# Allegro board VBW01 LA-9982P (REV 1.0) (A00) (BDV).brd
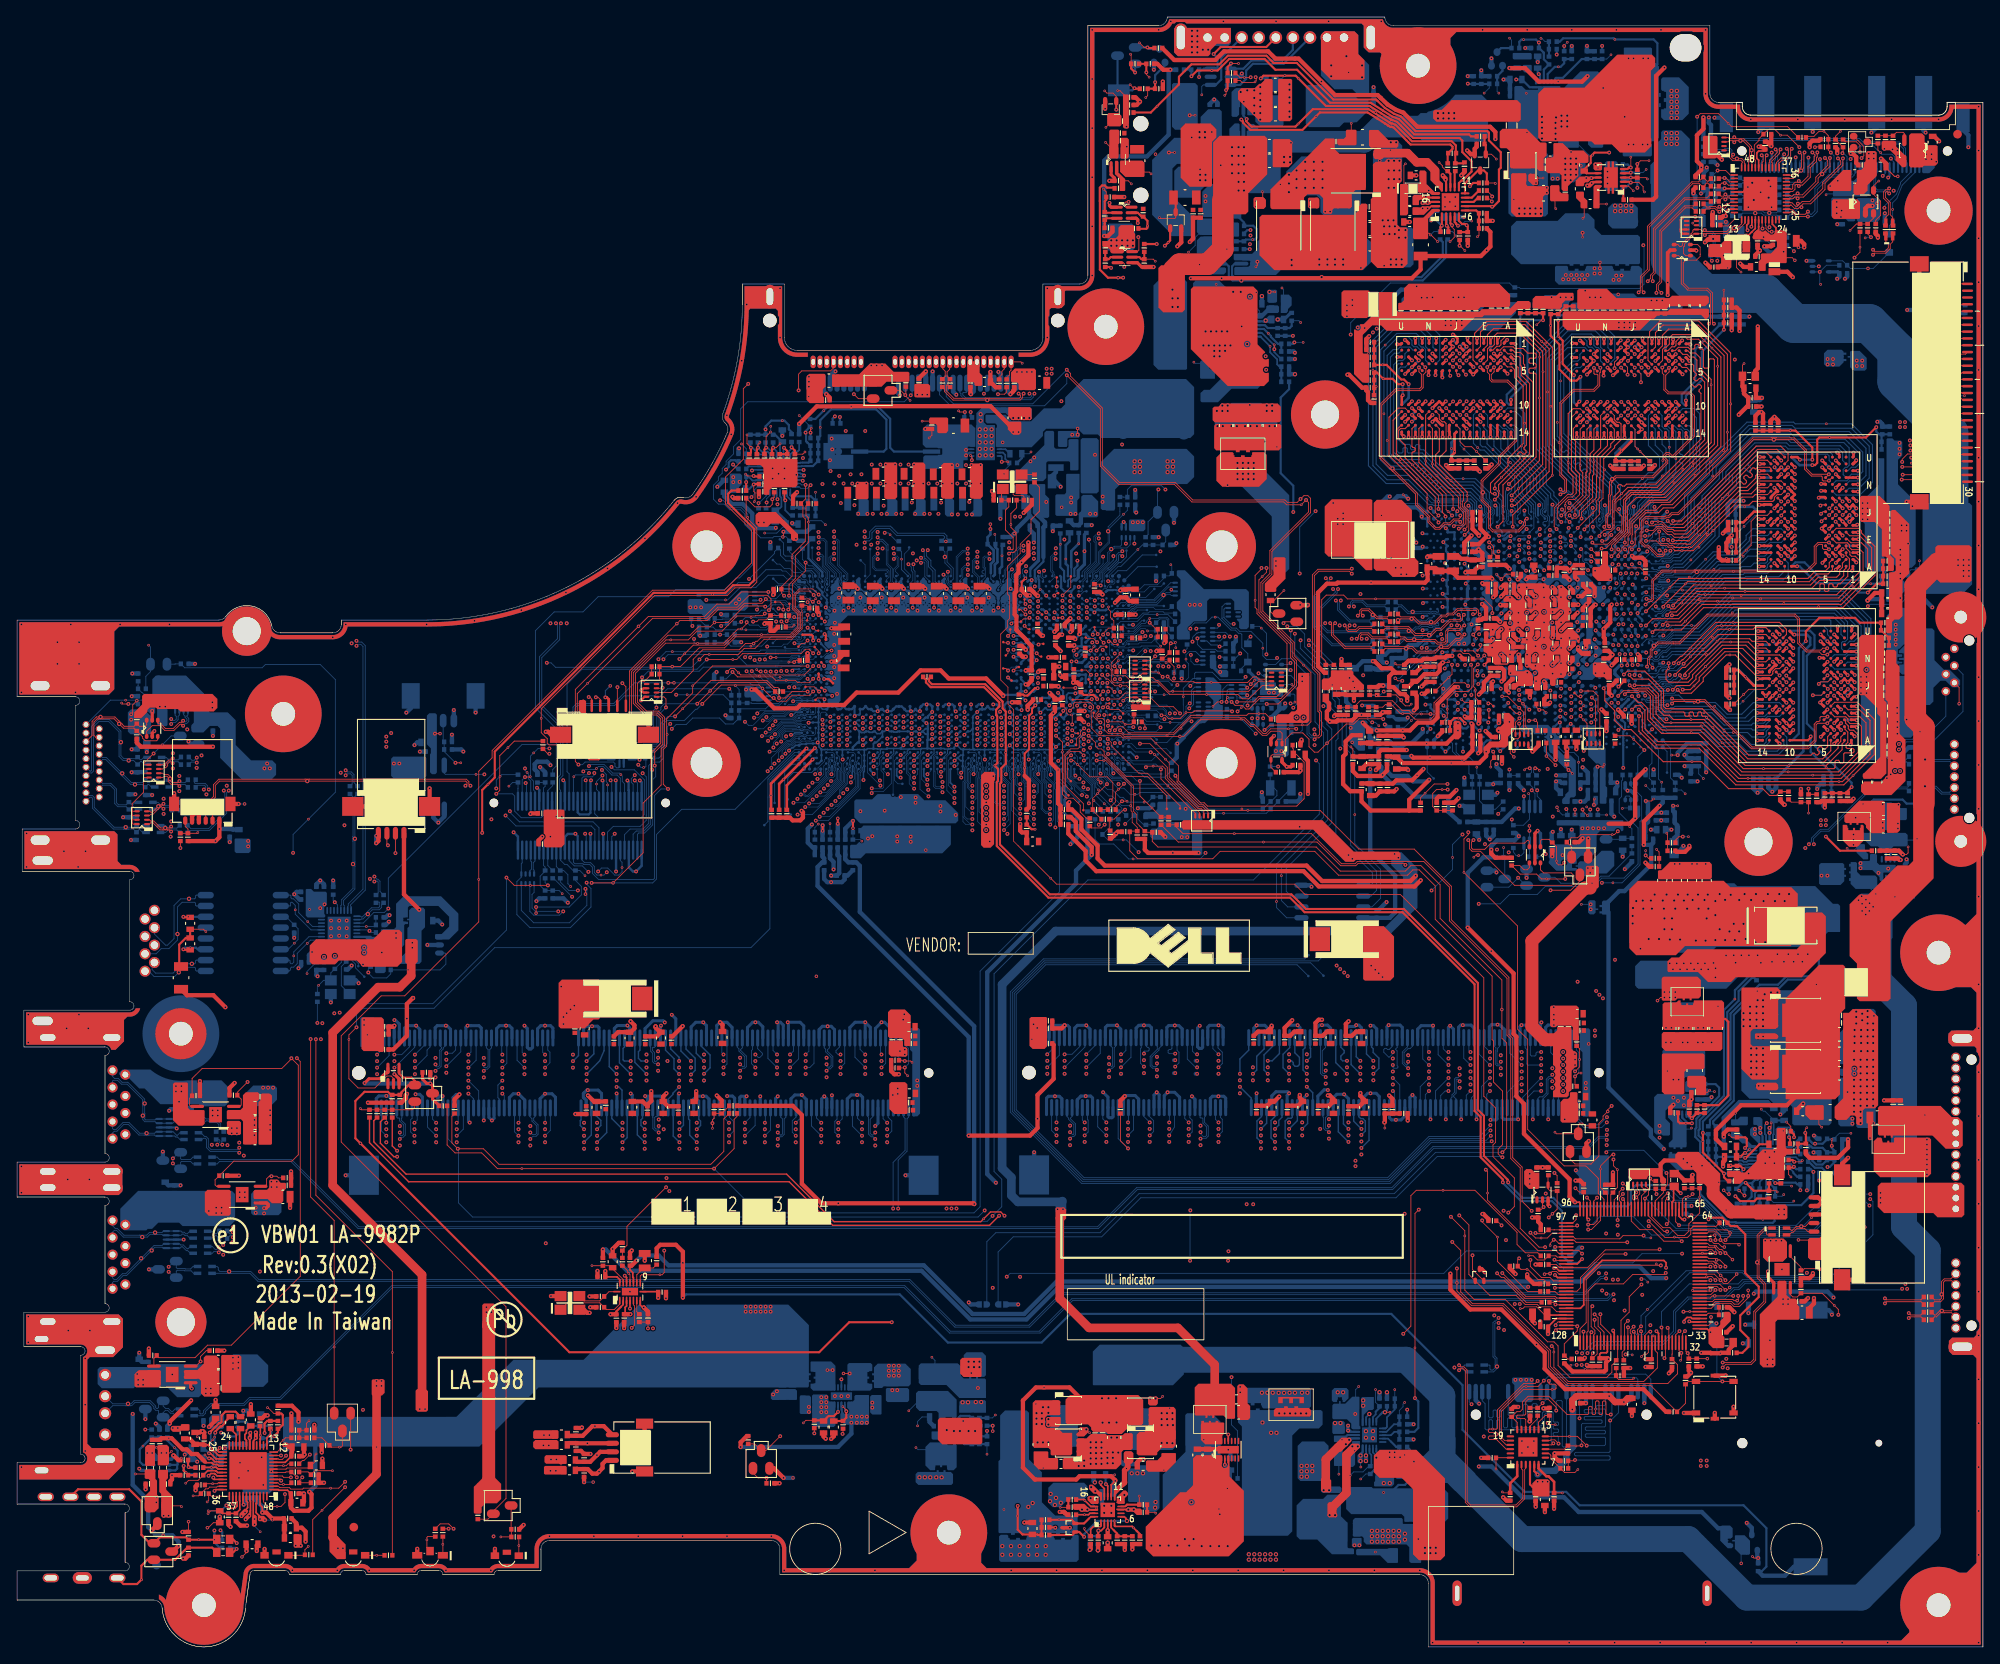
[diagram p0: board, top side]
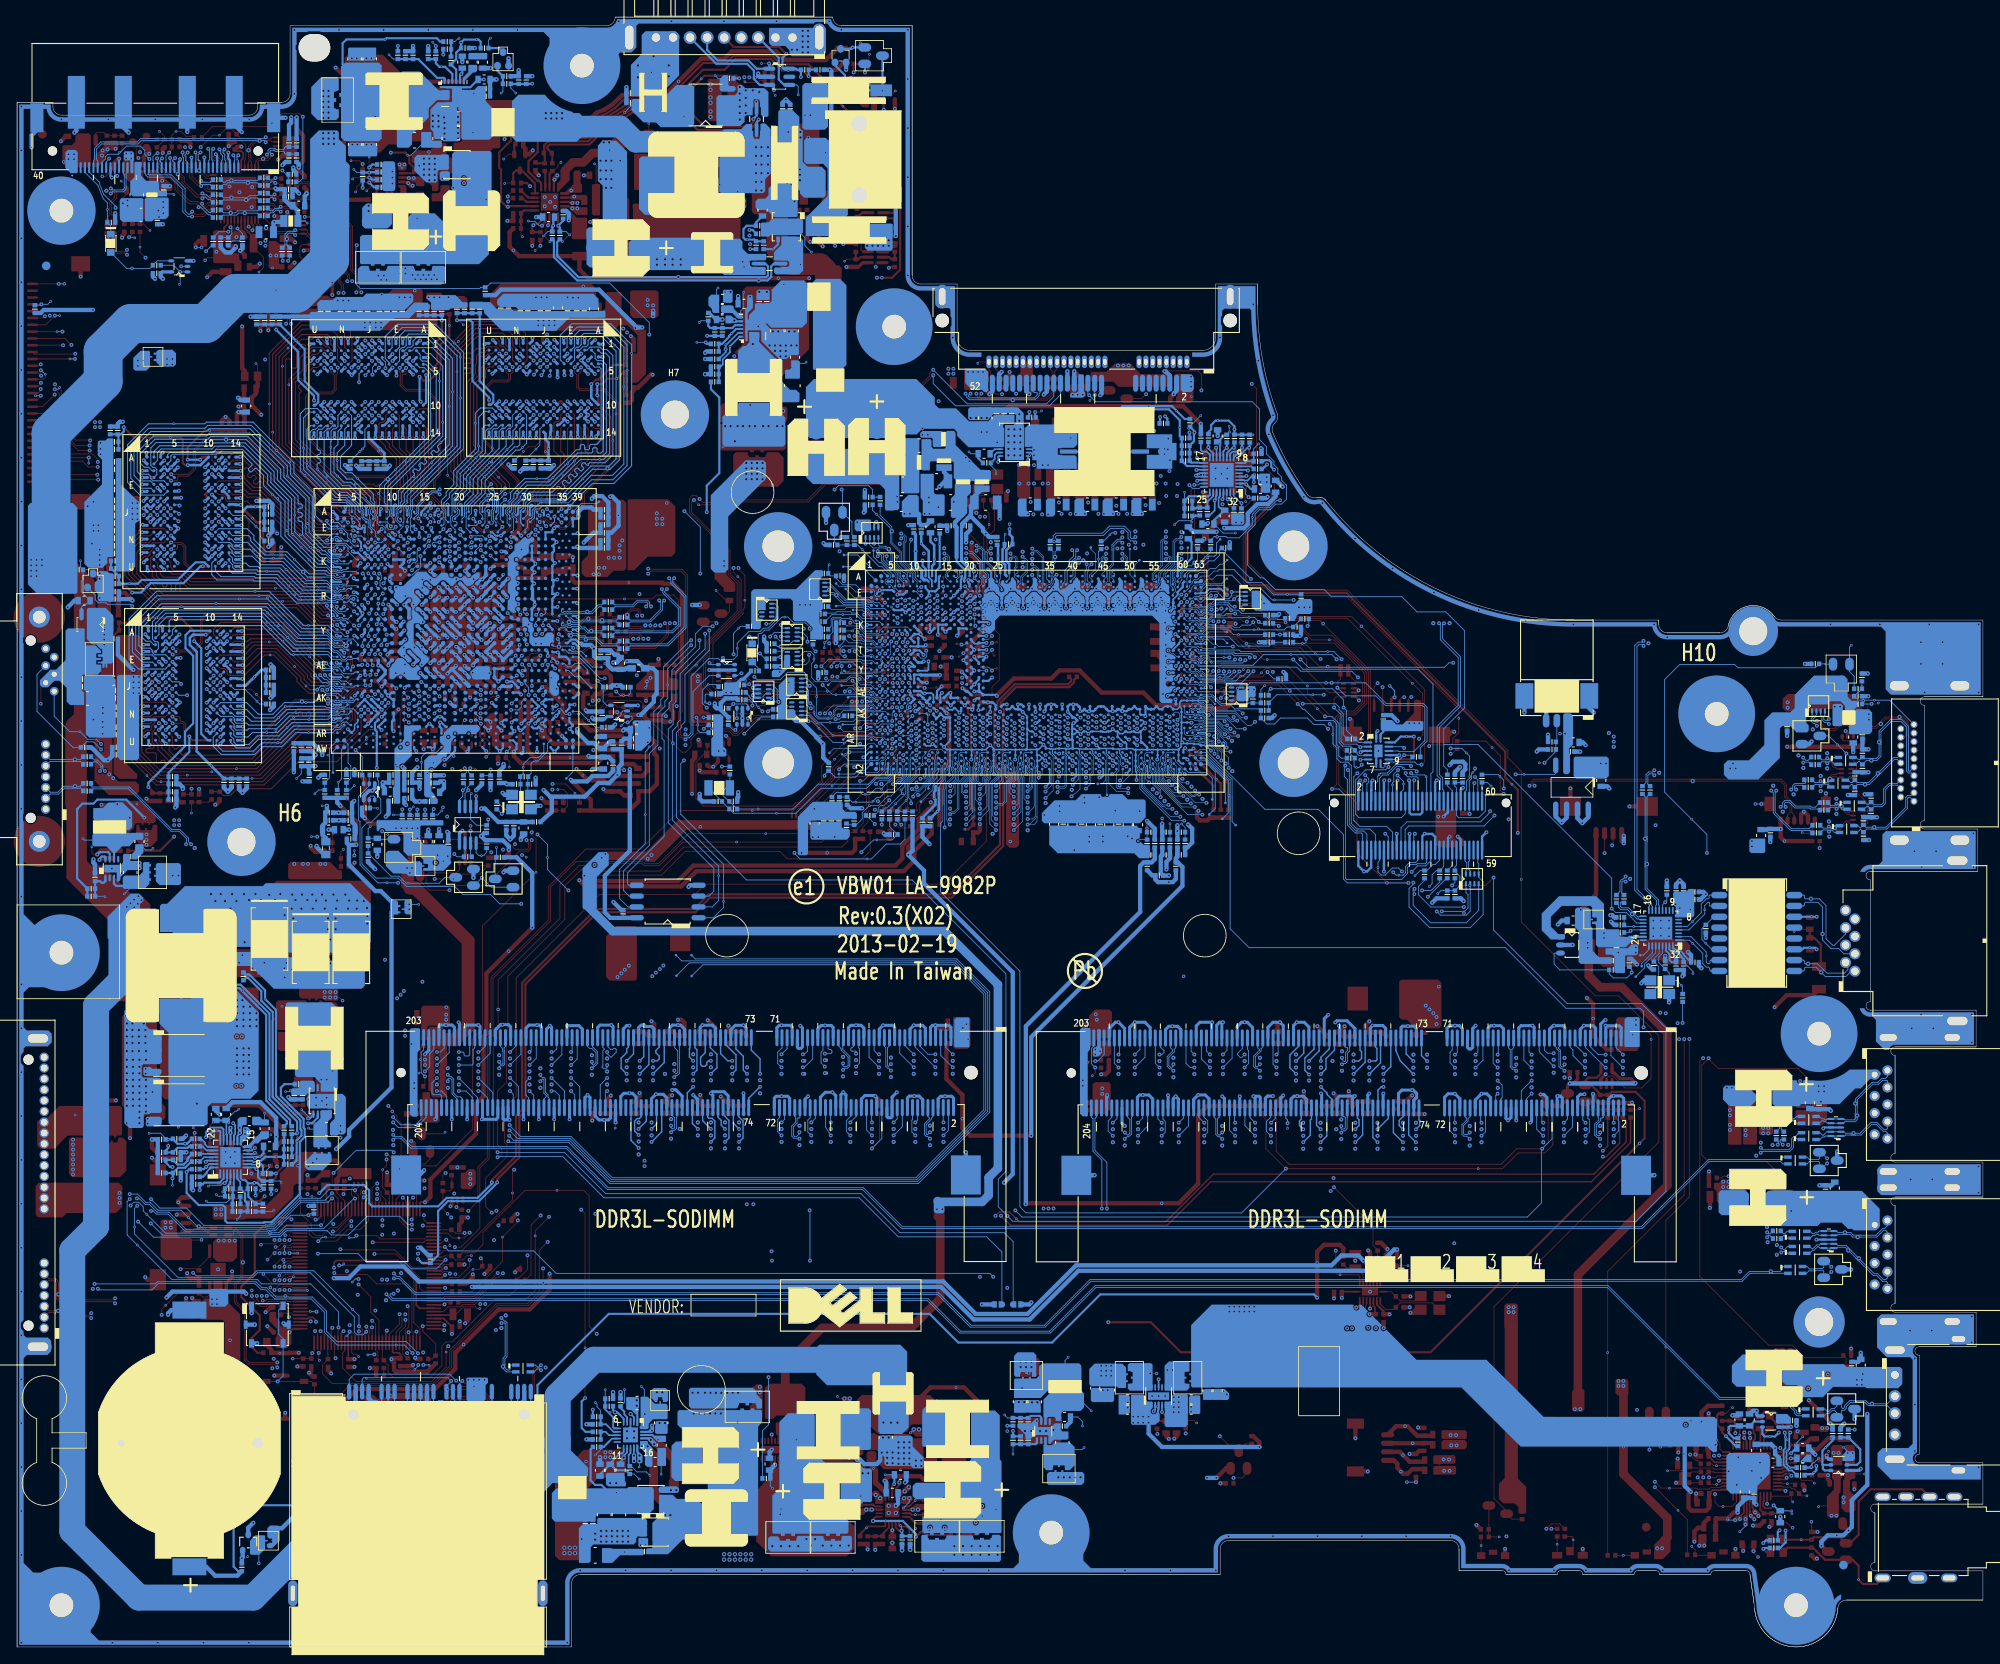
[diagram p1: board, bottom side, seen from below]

Outline 230.4 x 191.1 mm; copper layers: TOP, GND1, IN1, VCC, IN2, IN3, GND2, BOTTOM. Coordinates in mm from the lower left corner of the outline.

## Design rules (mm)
net group CLK_: nets CLK_CPU_ITP CLK_CPU_ITP#
net group CSI: nets CSIN CSIP
net group DIFFPAIR2: nets I2C1_SCL_TCH_PAD I2C1_SDA_TCH_PAD
net group DIFFPAIR3: nets CSCL CSDA
net group DIFFPAIR5: nets EC_SMB_CK2 EC_SMB_DA2
net group DIFFPAIR6: nets CPU_DPB_CTRLCLK_R CPU_DPB_CTRLDAT_R
net group DIFFPAIR9: nets CPU_EDP_AUX#_C CPU_EDP_AUX_C
net group EDID_CLK: nets EDID_CLK EDID_DATA
net group MIIC_SCL: nets MIIC_SCL MIIC_SDA
net group PCIE_PRX_LANTX_P3_C: nets PCIE_PRX_LANTX_N3_C PCIE_PRX_LANTX_P3_C
net group PECI-SINGLE: nets PECI_EC PECI_KB9012
net group SENSE: nets VCCSENSE VSSSENSE
net group SMB-15: nets SML1_SMBCLK SML1_SMBDATA
net group VCIN0_PH: nets ECAGND VCIN0_PH
net group WCKA0_0: nets WCKA0_0 WCKA0B_0
net group WCKA0_1: nets WCKA0_1 WCKA0B_1
net group WCKA1_0: nets WCKA1_0 WCKA1B_0
net group WCKA1_1: nets WCKA1_1 WCKA1B_1
net group WCKB0_0: nets WCKB0_0 WCKB0B_0
net group WCKB0_1: nets WCKB0_1 WCKB0B_1
net group WCKB1_0: nets WCKB1_0 WCKB1B_0
net group WCKB1_1: nets WCKB1_1 WCKB1B_1
net group 12: nets PCH_OPI_COMP PCH_PCIE_RCOMP SATA_IREF
net group ASYNC: nets DDR3_DRAMRST# DDR3_DRAMRST#_CPU H_PROCHOT# H_PROCHOT#_R H_VCCST_PWRGD_XDP XDP_OBS0_R XDP_OBS1_R
net group AUDIO: nets PCH_AZ_BITCLK PCH_AZ_CODEC_BITCLK PCH_AZ_CODEC_RST# PCH_AZ_CODEC_SDIN0 PCH_AZ_CODEC_SDOUT PCH_AZ_CODEC_SYNC PCH_AZ_RST# PCH_AZ_SDOUT PCH_AZ_SYNC
net group CLK: nets SUSCLK
net group CLK-SINGLE: nets CLK_PCI_LPC
net group CR_LOW: nets DSWODVREN INTRUDER# PCH_DPWROK PCH_INTVRMEN PCH_RSMRST#_R SYS_PWROK SYS_PWROK_R SYS_RESET#
net group DDRA-ADD: nets DDR_A_BS0 DDR_A_BS1 DDR_A_BS2 DDR_A_CAS# DDR_A_MA0 DDR_A_MA1 DDR_A_MA2 DDR_A_MA3 DDR_A_MA4 DDR_A_MA5 DDR_A_MA6 DDR_A_MA7 DDR_A_MA8 DDR_A_MA9 DDR_A_MA10 DDR_A_MA11 DDR_A_MA12 DDR_A_MA13 DDR_A_MA14 DDR_A_MA15 DDR_A_RAS# DDR_A_WE#
net group DDRA-CTL: nets DDR_CKE0_DIMMA DDR_CKE1_DIMMA DDR_CS0_DIMMA# DDR_CS1_DIMMA# M_ODT0 M_ODT1
net group DDRA-D0: nets DDR_A_D0 DDR_A_D1 DDR_A_D2 DDR_A_D3 DDR_A_D4 DDR_A_D5 DDR_A_D6 DDR_A_D7
net group DDRA-D1: nets DDR_A_D8 DDR_A_D9 DDR_A_D10 DDR_A_D11 DDR_A_D12 DDR_A_D13 DDR_A_D14 DDR_A_D15 DDR_A_DQS1 DDR_A_DQS#1
net group DDRA-D2: nets DDR_A_D16 DDR_A_D17 DDR_A_D18 DDR_A_D19 DDR_A_D20 DDR_A_D21 DDR_A_D22 DDR_A_D23
net group DDRA-D3: nets DDR_A_D24 DDR_A_D25 DDR_A_D26 DDR_A_D27 DDR_A_D28 DDR_A_D29 DDR_A_D30 DDR_A_D31
net group DDRA-D4: nets DDR_A_D32 DDR_A_D33 DDR_A_D34 DDR_A_D35 DDR_A_D36 DDR_A_D37 DDR_A_D38 DDR_A_D39
net group DDRA-D5: nets DDR_A_D40 DDR_A_D41 DDR_A_D42 DDR_A_D43 DDR_A_D44 DDR_A_D45 DDR_A_D46 DDR_A_D47
net group DDRA-D6: nets DDR_A_D48 DDR_A_D49 DDR_A_D50 DDR_A_D51 DDR_A_D52 DDR_A_D53 DDR_A_D54 DDR_A_D55
net group DDRA-D7: nets DDR_A_D56 DDR_A_D57 DDR_A_D58 DDR_A_D59 DDR_A_D60 DDR_A_D61 DDR_A_D62 DDR_A_D63
net group DDRB-ADD: nets DDR_B_BS0 DDR_B_BS1 DDR_B_BS2 DDR_B_CAS# DDR_B_MA0 DDR_B_MA1 DDR_B_MA2 DDR_B_MA3 DDR_B_MA4 DDR_B_MA5 DDR_B_MA6 DDR_B_MA7 DDR_B_MA8 DDR_B_MA9 DDR_B_MA10 DDR_B_MA11 DDR_B_MA12 DDR_B_MA13 DDR_B_MA14 DDR_B_MA15 DDR_B_RAS# DDR_B_WE#
net group DDRB-CTL: nets DDR_CKE2_DIMMB DDR_CKE3_DIMMB DDR_CS2_DIMMB# DDR_CS3_DIMMB# M_ODT2 M_ODT3
net group DDRB-D0: nets DDR_B_D0 DDR_B_D1 DDR_B_D2 DDR_B_D3 DDR_B_D4 DDR_B_D5 DDR_B_D6 DDR_B_D7
net group DDRB-D1: nets DDR_B_D8 DDR_B_D9 DDR_B_D10 DDR_B_D11 DDR_B_D12 DDR_B_D13 DDR_B_D14 DDR_B_D15
net group DDRB-D2: nets DDR_B_D16 DDR_B_D17 DDR_B_D18 DDR_B_D19 DDR_B_D20 DDR_B_D21 DDR_B_D22 DDR_B_D23
net group DDRB-D3: nets DDR_B_D24 DDR_B_D25 DDR_B_D26 DDR_B_D27 DDR_B_D28 DDR_B_D29 DDR_B_D30 DDR_B_D31
net group DDRB-D4: nets DDR_B_D32 DDR_B_D33 DDR_B_D34 DDR_B_D35 DDR_B_D36 DDR_B_D37 DDR_B_D38 DDR_B_D39
net group DDRB-D5: nets DDR_B_D40 DDR_B_D41 DDR_B_D42 DDR_B_D43 DDR_B_D44 DDR_B_D45 DDR_B_D46 DDR_B_D47
net group DDRB-D6: nets DDR_B_D48 DDR_B_D49 DDR_B_D50 DDR_B_D51 DDR_B_D52 DDR_B_D53 DDR_B_D54 DDR_B_D55
net group DDRB-D7: nets DDR_B_D56 DDR_B_D57 DDR_B_D58 DDR_B_D59 DDR_B_D60 DDR_B_D61 DDR_B_D62 DDR_B_D63
net group DP: nets CPU_DPB_AUX CPU_DPB_AUX# CPU_DPC_AUX CPU_DPC_AUX#
net group EDP: nets CPU_EDP_N0_C CPU_EDP_N1_C CPU_EDP_P0_C CPU_EDP_P1_C
net group HDA: nets AUD_HP_OUT_L_CN AUD_HP_OUT_R_CN HPOUT-L HPOUT-R MIC_IN MIC_IN_R RING2 RING2_R
net group HDMI: nets TMDS_L_TX0N TMDS_L_TX0P TMDS_L_TX1N TMDS_L_TX1P TMDS_L_TX2N TMDS_L_TX2P TMDS_L_TXCN TMDS_L_TXCP TMDS_TX0N TMDS_TX0P TMDS_TX1N TMDS_TX1P TMDS_TX2N TMDS_TX2P TMDS_TXCN TMDS_TXCP
net group KB: nets KSI0 KSI1 KSI2 KSI3 KSI4 KSI5 KSI6 KSI7 KSO0 KSO1 KSO2 KSO3 KSO4 KSO5 KSO6 KSO7 KSO8 KSO9 KSO10 KSO11 KSO12 KSO13 KSO14 KSO15 KSO16
net group LPC: nets LPC_LAD0 LPC_LAD1 LPC_LAD2 LPC_LAD3 LPC_LFRAME#
net group LVDS: nets EDP_AUX EDP_AUX# EDP_N0 EDP_N1 EDP_P0 EDP_P1 LVDS_A0+ LVDS_A0- LVDS_A1+ LVDS_A1- LVDS_A2+ LVDS_A2- LVDS_ACLK+ LVDS_ACLK- LVDS_B0+ LVDS_B0- LVDS_B1+ LVDS_B1- LVDS_B2+ LVDS_B2- LVDS_BCLK+ LVDS_BCLK-
net group PCIE: nets PCIE_PRX_LANTX_N3 PCIE_PRX_LANTX_P3 PCIE_PTX_LANRX_N3 PCIE_PTX_LANRX_P3 PCIE_PTX_WLANRX_N4_C PCIE_PTX_WLANRX_P4_C
net group PEG: nets PEG_CTX_GRX_N0 PEG_CTX_GRX_N1 PEG_CTX_GRX_N2 PEG_CTX_GRX_N3 PEG_CTX_GRX_P0 PEG_CTX_GRX_P1 PEG_CTX_GRX_P2 PEG_CTX_GRX_P3
net group POWER: nets +0.675VSP +1.5VS +1.5VSP +1.5VSP_ON +1.35VP +3V_WLAN +3VALW_PCH +3VALWP +3VLP +3VS_CAM +5V_HDD +5V_PVDD +5V_USB_PWR1 +5V_USB_PWR2 +5V_USB_PWR3 +5V_USB_PWR4 +5VA +5VALWP +5VS_ODD +5VS_TOUCH +AVCC33 +DIMM1_VREF_DQ +DIMM2_VREF_DQ +EC_VCCA +FAN_POWER +INV_PWR_SRC +LAN_IO +LAN_VDD +LCDVDD +MIC2-VREFO +PCH_VCCDSW +PCH_VCCDSW_R +RTCBATT +RTCVCC +SM_VREF_CA +SM_VREF_CA_DIMM +SM_VREF_DQ0 +SM_VREF_DQ0_DIMM1 +SM_VREF_DQ1 +SM_VREF_DQ1_DIMM2 +SW_LX +V18R +VCC_3IN1 +VCC_PWR_SRC +VCCIO_OUT +VCCIOA_OUT +VCHGR +VDISPLAY_VCC
net group RCOMP: nets SM_RCOMP0 SM_RCOMP1 SM_RCOMP2
net group RTC: nets PCH_RTCRST# PCH_RTCX1 PCH_RTCX2 SRTCRST#
net group SATA: nets SATA_PRX_DTX_N0 SATA_PRX_DTX_N0_C SATA_PRX_DTX_N1 SATA_PRX_DTX_P0 SATA_PRX_DTX_P0_C SATA_PRX_DTX_P1 SATA_PTX_DRX_N0 SATA_PTX_DRX_N1 SATA_PTX_DRX_P0 SATA_PTX_DRX_P1
net group SMB_10: nets DDR_XDP_SMBCLK_R1 DDR_XDP_SMBDAT_R1 SML0CLK SML0DATA
net group SPI: nets PCH_SPI_CLK PCH_SPI_CLK_R PCH_SPI_CS0# PCH_SPI_HOLD1# PCH_SPI_HOLD# PCH_SPI_MISO PCH_SPI_MISO_1 PCH_SPI_MOSI PCH_SPI_MOSI_1 PCH_SPI_WP1# PCH_SPI_WP#
net group SPK: nets INT-SPK-L+ INT-SPK-L- INT-SPK-R+ INT-SPK-R-
net group SVID: nets H_CPU_SVIDALRT# H_CPU_SVIDCLK H_CPU_SVIDDATA VR_SVID_ALRT# VR_SVID_CLK VR_SVID_DAT
net group THERMTRIP-SINGLE: nets H_THERMTRIP#
net group USB20: nets USB20_CAM_N7_R USB20_CAM_P7_R USB20_CR_N6_R USB20_CR_P6_R USB20_JUSB3_N2 USB20_JUSB3_N2_R USB20_JUSB3_P2 USB20_JUSB3_P2_R USB20_USBDB_N3_R USB20_USBDB_P3_R
net group USB30: nets USB3RN1_JUSB2 USB3RN1_JUSB2_R USB3RN2_JUSB1 USB3RN2_JUSB1_R USB3RP1_JUSB2 USB3RP1_JUSB2_R USB3RP2_JUSB1 USB3RP2_JUSB1_R USB3TN1_JUSB2_C USB3TN1_JUSB2_R USB3TN2_JUSB1_C USB3TN2_JUSB1_R USB3TP1_JUSB2_C USB3TP1_JUSB2_R USB3TP2_JUSB1_C USB3TP2_JUSB1_R
net group VRAMA1-D0: nets DDBIA1_0 DQA1_0 DQA1_1 DQA1_2 DQA1_3 DQA1_4 DQA1_5 DQA1_6 DQA1_7 EDCA1_0
net group VRAMA1-D1: nets DDBIA1_1 DQA1_8 DQA1_9 DQA1_10 DQA1_11 DQA1_12 DQA1_13 DQA1_14 DQA1_15 EDCA1_1
net group VRAMA1-D2: nets DDBIA1_2 DQA1_16 DQA1_17 DQA1_18 DQA1_19 DQA1_20 DQA1_21 DQA1_22 DQA1_23 EDCA1_2
net group VRAMA1-D3: nets DDBIA1_3 DQA1_24 DQA1_25 DQA1_26 DQA1_27 DQA1_28 DQA1_29 DQA1_30 DQA1_31 EDCA1_3
net group VRAMA-ADD: nets ADBIA0 ADBIA1 CASA0# CASA1# CKEA0 CKEA1 CSA0#_0 CSA1#_0 MAA0_0 MAA0_1 MAA0_2 MAA0_3 MAA0_4 MAA0_5 MAA0_6 MAA0_7 MAA0_8 MAA1_0 MAA1_1 MAA1_2 MAA1_3 MAA1_4 MAA1_5 MAA1_6 MAA1_7 MAA1_8 RASA0# RASA1# WEA0# WEA1#
net group VRAMA-D0: nets DDBIA0_0 DQA0_0 DQA0_1 DQA0_2 DQA0_3 DQA0_4 DQA0_5 DQA0_6 DQA0_7 EDCA0_0
net group VRAMA-D1: nets DDBIA0_1 DQA0_8 DQA0_9 DQA0_10 DQA0_11 DQA0_12 DQA0_13 DQA0_14 DQA0_15 EDCA0_1
net group VRAMA-D2: nets DDBIA0_2 DQA0_16 DQA0_17 DQA0_18 DQA0_19 DQA0_20 DQA0_21 DQA0_22 DQA0_23 EDCA0_2
net group VRAMA-D3: nets DDBIA0_3 DQA0_24 DQA0_25 DQA0_26 DQA0_27 DQA0_28 DQA0_29 DQA0_30 DQA0_31 EDCA0_3
net group VRAMB0-D0: nets DDBIB0_0 DQB0_0 DQB0_1 DQB0_2 DQB0_3 DQB0_4 DQB0_5 DQB0_6 DQB0_7 EDCB0_0
net group VRAMB0-D1: nets DDBIB0_1 DQB0_8 DQB0_9 DQB0_10 DQB0_11 DQB0_12 DQB0_13 DQB0_14 DQB0_15 EDCB0_1
net group VRAMB0-D2: nets DDBIB0_2 DQB0_16 DQB0_17 DQB0_18 DQB0_19 DQB0_20 DQB0_21 DQB0_22 DQB0_23 EDCB0_2
net group VRAMB0-D3: nets DDBIB0_3 DQB0_24 DQB0_25 DQB0_26 DQB0_27 DQB0_28 DQB0_29 DQB0_30 DQB0_31 EDCB0_3
net group VRAMB1-D0: nets DDBIB1_0 DQB1_0 DQB1_1 DQB1_2 DQB1_3 DQB1_4 DQB1_5 DQB1_6 DQB1_7 EDCB1_0
net group VRAMB1-D1: nets DDBIB1_1 DQB1_8 DQB1_9 DQB1_10 DQB1_11 DQB1_12 DQB1_13 DQB1_14 DQB1_15 EDCB1_1
net group VRAMB1-D2: nets DDBIB1_2 DQB1_16 DQB1_17 DQB1_18 DQB1_19 DQB1_20 DQB1_21 DQB1_22 DQB1_23 EDCB1_2
net group VRAMB1-D3: nets DDBIB1_3 DQB1_24 DQB1_25 DQB1_26 DQB1_27 DQB1_28 DQB1_29 DQB1_30 DQB1_31 EDCB1_3
net group VRAMB-ADD: nets ADBIB0 ADBIB1 CASB0# CASB1# CKEB0 CKEB1 CSB0#_0 CSB1#_0 DRAM_RST# DRAM_RST#_R MAB0_0 MAB0_1 MAB0_2 MAB0_3 MAB0_4 MAB0_5 MAB0_6 MAB0_7 MAB0_8 MAB1_0 MAB1_1 MAB1_2 MAB1_3 MAB1_4 MAB1_5 MAB1_6 MAB1_7 MAB1_8 RASB0# RASB1# WEB0# WEB1#
nets with their own width: min track width 0.254; nets +1.8VSP +3VALW +VGA_CORE +VGA_PCIEP CLK_BIASREF
nets with their own width: min track width 0.508; nets +0.675VS +1.2VSP_B+ +1.05V_PGOOD +1.05VS_APLLOPI +1.05VS_ASATA3PLL +1.05VS_AUSB3PLL +1.05VS_AXCK_DCB +1.05VS_AXCK_LCPLL +1.05VSP +1.8VGS +1.8VS +1.8VSP_ON +1.35V +1.35V_MEM_GFX +1.35VGPUP +1.35VS_VGA +3VALW_PCH_GATE +3VGS +3VS +3VS_RT +5VALW +5VS +AVDD +BIF_VDDC +CHGRTC +CPU_CORE +DPAB_VDD10 +DPAB_VDD18 +DPCD_VDD10 +DPCD_VDD18 +DPEF_VDD10 +DPEF_VDD18 +DPLL_PVDD +DPLL_VDDC +LCDVDD_CONN +MPV18 +PCIE_PVDD +PCIE_VDDR +SPV10 +SPV18 +TSVDD +VCCIO_OUT_R +VCCRTCEXT +VDD1DI +VDD_MEM15_REFDA +VDD_MEM15_REFDB +VDD_MEM15_REFSA +VDD_MEM15_REFSB +VDDC_CT +VDDCI +VDDCIP +VDDR4 +VREFG_GPU EDP_COMP GND GNDA
nets with their own width: min track width 1.016; nets +DVCC33
nets with their own width: min track width 1.27; nets +1.05VS
nets with their own width: min track width 1.524; nets +SWR_V12

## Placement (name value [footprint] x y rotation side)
C35  -  [C_0402NEW]  107.79 96.92 270 bottom
C36  -  [C_0402NEW]  105.63 96.92 270 bottom
C37  -  [C_0402NEW]  103.47 96.92 270 bottom
C38  -  [C_0402NEW]  101.31 96.92 270 bottom
C39  -  [C_0603NEW]  108.87 97.17 270 bottom
C41  -  [C_0603NEW]  106.71 97.1 270 bottom
C42  -  [C_0603NEW]  104.55 97.1 270 bottom
C45  -  [C_0603NEW]  102.39 97.1 270 bottom
C50  -  [C_0402NEW]  123.22 118.32 270 top
C51  -  [C_0402NEW]  149.5 105.74 0 top
C52  -  [C_0402NEW]  124.68 111.95 90 top
C53  -  [C_0402NEW]  124.55 119.68 180 top
C54  -  [C_0402NEW]  134.08 97.31 270 bottom
C55  -  [C_0402NEW]  134.97 97.31 270 bottom
C56  -  [C_0402NEW]  135.86 97.31 270 bottom
C57  -  [C_0402NEW]  130.34 121.04 180 top
C58  -  [C_0402NEW]  120.48 131.46 0 bottom
C59  -  [C_1206NEW]  119.66 134.19 0 bottom
C60  -  [C_0603NEW]  131.03 122.63 90 top
C61  -  [C_0402NEW]  122.79 119.71 180 top
C62  -  [C_0402NEW]  129.95 123.06 90 top
C63  -  [C_0402NEW]  125.31 130.62 90 bottom
C64  -  [C_0402NEW]  118.33 96.42 270 top
C65  -  [C_1206NEW]  125.44 134.06 0 bottom
C66  -  [C_0603NEW]  119.73 94.44 180 top
C67  -  [C_0402NEW]  119.99 111.07 180 top
C68  -  [C_0402NEW]  123.85 114.64 270 top
C69  -  [C_0402NEW]  118.9 114.51 270 top
C70  -  [C_1206NEW]  125.3 136.26 0 bottom
C71  -  [C_0402NEW]  121.69 118.39 270 top
C72  -  [C_0603NEW]  100.23 97.1 270 bottom
C73  -  [C_0402NEW]  122.72 116.03 180 top
C74  -  [C_0603NEW]  99.03 97.1 270 bottom
C75  -  [C_0402NEW]  117.43 110.75 90 top
C76  -  [C_0402NEW]  120.29 112.66 0 top
C77  -  [C_0402NEW]  121.63 110.17 90 top
C78  -  [C_0603NEW]  122.9 113.74 180 top
C81  -  [C_0402NEW]  124.46 109.75 270 top
C82  -  [C_0603NEW]  122.9 114.95 180 top
C83  -  [C_0402NEW]  119.6 119.97 270 top
C84  -  [C_1206NEW]  121.3 136.66 0 bottom
C85  -  [C_0402NEW]  119.61 131.46 180 bottom
C86  -  [C_1206NEW]  118.2 134.19 180 bottom
C87  -  [C_0402NEW]  120.3 113.54 90 top
C88  -  [C_0402NEW]  117.5 117.37 270 top
C2305  -  [C_0603NEW]  99.53 29.03 0 bottom
C2306  -  [C_0603NEW]  99.53 27.82 0 bottom
C2307  -  [C_0805NEW]  102.58 30.96 270 bottom
C2308  -  [C_0603NEW]  104.04 31.06 270 bottom
C2309  -  [C_0603NEW]  95.72 26.49 270 top
C2310  -  [C_0805NEW]  142.31 27.51 0 top
C2311  -  [C_0603NEW]  138.33 21.79 90 top
C2312  -  [C_0603NEW]  142.21 29.03 0 top
C2313  -  [C_0603NEW]  139.54 21.79 90 top
C2314  -  [C_0603NEW]  142.21 20.74 90 bottom
C2316  -  [C_0603NEW]  93.5 27.82 180 bottom
C2318  -  [C_0603NEW]  93.5 29.03 180 bottom
C2322  -  [C_0603NEW]  94.52 26.49 270 top
C2323  -  [C_0603NEW]  89.69 30.74 270 bottom
C2324  -  [C_0603NEW]  90.9 30.74 270 bottom
C2326  -  [C_0402NEW]  142.55 114.97 180 bottom
C2327  -  [C_0402NEW]  159.36 85.48 90 bottom
C5212  -  [C_0402NEW]  83.2 117.8 0 bottom
CA1  -  [C_0603NEW]  28.54 25.92 90 bottom
CA2  -  [C_0603NEW]  27.33 25.92 90 bottom
CA21  -  [C_0402NEW]  34.43 20.2 0 top
CA22  -  [C_0402NEW]  34.43 19.25 0 top
CA23  -  [C_0603NEW]  20.41 22.11 0 bottom
CA24  -  [C_0402NEW]  22.46 17.98 180 top
CA25  -  [C_0402NEW]  21.1 19 0 top
CA29  -  [C_0402NEW]  65.5 24.76 90 top
CA30  -  [C_0402NEW]  65.5 23.9 270 top
CA31  -  [C_0402NEW]  66.45 21.71 90 top
CA32  -  [C_0402NEW]  66.45 20.85 270 top
CA33  -  [C_0402NEW]  20.09 12.57 90 top
CA38  -  [C_0402NEW]  15.98 19.12 180 top
CA39  -  [C_0402NEW]  20.09 11.64 270 top
CA40  -  [C_0402NEW]  17.05 19.09 0 top
CA51  -  [C_0402NEW]  21.94 23.68 90 top
CA53  -  [C_0603NEW]  27.91 17.47 90 bottom
CA54  -  [C_0402NEW]  26.83 17.46 90 bottom
CA55  -  [C_0603NEW]  31.33 13.98 0 top
CA56  -  [C_0402NEW]  31.26 15.06 0 top
CA57  -  [C_0603NEW]  32.1 16.9 0 top
CA58  -  [C_0402NEW]  32.08 17.98 0 top
CA59  -  [C_0603NEW]  32.22 23.44 0 top
CA60  -  [C_0402NEW]  32.15 22.36 0 top
CA61  -  [C_0603NEW]  23.75 15.96 270 top
CA62  -  [C_0603NEW]  20.41 23.32 0 bottom
CA63  -  [C_0603NEW]  23.75 14.56 90 bottom
CA64  -  [C_0603NEW]  35.78 21.28 180 top
CA65  -  [C_0402NEW]  32.15 24.52 0 top
CA67  -  [C_0603NEW]  24.98 25.6 90 top
CA68  -  [C_0603NEW]  26.19 25.6 90 top
CA69  -  [C_0402NEW]  33.06 25.41 180 top
CA71  -  [C_0603NEW]  20.86 23.76 90 top
CA74  -  [C_0603NEW]  27.4 25.92 90 top
CC1  -  [C_0402NEW]  146 99.13 0 bottom
CC2  -  [C_0402NEW]  148.7 99.13 180 bottom
CC3  -  [C_0402NEW]  129.49 95.58 0 top
CC4  -  [C_0402NEW]  133.96 95.51 180 top
CC5  -  [C_0402NEW]  127.21 95.26 0 bottom
CC6  -  [C_0402NEW]  118.92 134.46 180 top
CC7  -  [C_0402NEW]  114.45 134.46 0 top
CC8  -  [C_0402NEW]  97.05 95.53 0 bottom
CC9  -  [C_0402NEW]  94.41 95.53 180 bottom
CC10  -  [C_0402NEW]  96.19 95.53 180 bottom
CC11  -  [C_0402NEW]  149.5 103.39 0 top
CC13  -  [C_0402NEW]  70.27 108.34 90 bottom
CC14  -  [C_0402NEW]  61.95 97.74 180 top
CC15  -  [C_0402NEW]  62.03 94.13 180 top
CC16  -  [C_0402NEW]  61.89 88.68 270 bottom
CC17  -  [C_0402NEW]  61.89 101.36 90 bottom
CC18  -  [C_0402NEW]  158.88 117.94 0 bottom
CC19  -  [C_0402NEW]  158.88 117.05 0 bottom
CC20  -  [C_0402NEW]  160.66 119.46 0 bottom
CC21  -  [C_0402NEW]  160.66 118.57 0 bottom
CC22  -  [C_0402NEW]  158.88 120.73 0 bottom
CC23  -  [C_0402NEW]  158.88 119.84 0 bottom
CC24  -  [C_0402NEW]  160.66 122.51 0 bottom
CC25  -  [C_0402NEW]  160.66 121.62 0 bottom
CC26  -  [C_0603NEW]  136.93 97.29 270 bottom
CC32  -  [C_0402NEW]  39.91 100.01 90 bottom
CC40  -  [C_0402NEW]  39.02 100.01 90 bottom
CD1  -  [C_0402NEW]  42.62 71.83 0 top
CD2  -  [C_0402NEW]  42.62 72.72 0 top
CD3  -  [C_0402NEW]  51.27 62.55 90 top
CD4  -  [C_0402NEW]  73.88 62.48 90 top
CD5  -  [C_0402NEW]  68.99 63.05 90 top
CD6  -  [C_0402NEW]  66.7 63.4 270 top
CD7  -  [C_0402NEW]  65.37 72.01 90 top
CD8  -  [C_0402NEW]  69.94 70.67 90 top
CD9  -  [C_0402NEW]  77.5 62.48 90 top
CD10  -  [C_0402NEW]  76.7 70.69 90 top
CD11  -  [C_0402NEW]  73.63 70.67 90 top
CD12  -  [C_0603NEW]  75.72 62.56 90 top
CD13  -  [C_0603NEW]  75.47 70.69 90 top
CD14  -  [C_0603NEW]  82.68 70.76 90 top
CD15  -  [C_D3]  73.27 76.02 180 top
CD16  -  [C_0603NEW]  67.91 62.56 90 top
CD17  -  [C_0603NEW]  72.1 62.56 90 top
CD18  -  [C_0603NEW]  79.34 62.56 90 top
CD19  -  [C_0603NEW]  66.51 71.77 90 top
CD20  -  [C_0603NEW]  71.78 70.69 90 top
CD21  -  [C_0402NEW]  81.69 62.55 90 top
CD22  -  [C_0402NEW]  82.58 62.55 90 top
CD23  -  [C_0402NEW]  47.51 67.36 0 top
CD24  -  [C_0402NEW]  105.26 70.75 180 top
CD25  -  [C_0402NEW]  105.26 71.64 180 top
CD26  -  [C_0402NEW]  105.01 62.94 180 top
CD27  -  [C_0402NEW]  104.94 63.83 180 top
CD28  -  [C_0603NEW]  105.29 64.91 180 top
CD29  -  [C_0603NEW]  105.25 72.72 180 top
CD30  -  [C_0402NEW]  102.58 70.74 90 top
CD31  -  [C_0402NEW]  103.47 70.74 90 top
CD32  -  [C_0402NEW]  120.41 73.42 0 top
CD33  -  [C_0402NEW]  120.41 72.53 0 top
CD34  -  [C_0402NEW]  129.31 62.55 90 top
CD35  -  [C_0402NEW]  152.49 62.55 90 top
CD36  -  [C_0402NEW]  148.87 62.55 90 top
CD37  -  [C_0402NEW]  145.25 62.55 90 top
CD38  -  [C_0402NEW]  156.05 62.48 90 top
CD39  -  [C_0402NEW]  155.73 70.74 90 top
CD40  -  [C_0402NEW]  152.17 70.74 90 top
CD41  -  [C_0402NEW]  148.56 70.74 90 top
CD42  -  [C_0402NEW]  144.94 70.74 90 top
CD43  -  [C_0603NEW]  150.65 62.56 90 top
CD44  -  [C_0603NEW]  147.03 62.56 90 top
CD45  -  [C_0603NEW]  154.27 62.56 90 top
CD46  -  [C_0603NEW]  146.78 70.75 90 top
CD47  -  [C_0603NEW]  150.33 70.75 90 top
CD48  -  [C_0603NEW]  153.95 70.75 90 top
CD49  -  [C_0603NEW]  157.57 70.75 90 top
CD50  -  [C_0603NEW]  157.89 62.56 90 top
CD51  -  [C_D3]  152.68 82.98 0 top
CD52  -  [C_0402NEW]  160.3 62.55 90 top
CD53  -  [C_0402NEW]  161.19 62.55 90 top
CD54  -  [C_0402NEW]  183.62 72.27 180 top
CD55  -  [C_0402NEW]  183.62 73.16 180 top
CD56  -  [C_0402NEW]  183.56 62.56 180 top
CD57  -  [C_0402NEW]  183.56 63.45 180 top
CD58  -  [C_0603NEW]  183.83 64.53 180 top
CD59  -  [C_0603NEW]  183.54 74.24 180 top
CD60  -  [C_0402NEW]  180.94 72.26 90 top
CD61  -  [C_0402NEW]  181.83 72.26 90 top
CE1  -  [C_0402NEW]  199.41 36.9 0 top
CE2  -  [C_0402NEW]  191.54 33.74 270 top
CE5  -  [C_0402NEW]  178.51 37.54 0 top
CE6  -  [C_0402NEW]  185.49 32.93 90 top
CE7  -  [C_0402NEW]  200.61 34.49 0 top
CE8  -  [C_0402NEW]  196.31 53.78 90 top
CE9  -  [C_0402NEW]  200.45 49.73 180 top
CE11  -  [C_0402NEW]  199.47 39.83 0 top
CE12  -  [C_0402NEW]  187.4 31.82 0 top
CE15  -  [C_0402NEW]  178.08 55.31 90 top
CE16  -  [C_0805NEW]  179.31 39 180 top
CE18  -  [C_0402NEW]  178.58 44.84 0 top
CE19  -  [C_0402NEW]  179.48 55.31 90 top
CE20  -  [C_0402NEW]  195.55 30.8 90 top
CE22  -  [C_0603NEW]  48.73 106.06 180 bottom
CE23  -  [C_0402NEW]  48.81 104.98 180 bottom
CE24  -  [C_0402NEW]  50.05 106.12 0 bottom
CE25  -  [C_0603NEW]  44.73 102.31 270 bottom
CE26  -  [C_0402NEW]  183.61 53.34 90 top
CE27  -  [C_0402NEW]  184.62 33.84 270 top
CE28  -  [C_0402NEW]  188.31 33.61 270 top
CE29  -  [C_0402NEW]  193.96 33.74 270 top
CE30  -  [C_0402NEW]  175.87 44.65 180 top
CE31  -  [C_0402NEW]  196.85 33.81 270 top
CE32  -  [C_0402NEW]  173.36 49.97 180 top
CE33  -  [C_0402NEW]  182.2 33.77 0 top
CG1  -  [C_0402NEW]  71.83 44.7 90 top
CG2  -  [C_0402NEW]  71.15 39.01 270 top
CG3  -  [C_0402NEW]  75.14 41.6 0 top
CG4  -  [C_0402NEW]  68.94 43.38 180 top
CG5  -  [C_0805NEW]  73.56 44.44 90 top
CG6  -  [C_0603NEW]  69.8 44.46 90 top
CG7  -  [C_0402NEW]  73.94 38.1 90 top
CG8  -  [C_0402NEW]  68.81 39.83 180 top
CG9  -  [C_0402NEW]  68.81 41.1 180 top
CG10  -  [C_0402NEW]  70.23 39 270 top
CG11  -  [C_0402NEW]  70.95 46.47 90 top
CI1  -  [C_MP6VLPS220MC4R2]  22.88 64.34 180 bottom
CI2  -  [C_0402NEW]  19.21 63.97 270 bottom
CI3  -  [C_0402NEW]  23.33 60.41 270 bottom
CI4  -  [C_0402NEW]  24.22 60.41 270 bottom
CI6  -  [C_0805NEW]  30.29 52.78 0 top
CI7  -  [C_0402NEW]  31.19 54.11 0 top
CI8  -  [C_MP6VLPS220MC4R2]  23.58 52.72 180 bottom
CI9  -  [C_0402NEW]  18.44 53.21 90 bottom
CI10  -  [C_0402NEW]  23.7 47.88 0 bottom
CI11  -  [C_0402NEW]  23.7 48.78 0 bottom
CI12  -  [C_0805NEW]  27.04 61.48 0 top
CI13  -  [C_0402NEW]  25.81 64.69 180 top
CI14  -  [C_0402NEW]  28.01 64.53 0 top
CI15  -  [C_0402NEW]  20.51 64.63 0 top
CI16  -  [C_0402NEW]  22.56 34.75 0 top
CI17  -  [C_0402NEW]  23.7 55.26 0 top
CI18  -  [C_0805NEW]  27.03 59.66 0 top
CI19  -  [C_0402NEW]  15.4 32.51 90 bottom
CI20  -  [C_MP6VLPS220MC4R2]  21.68 31.51 180 bottom
CI21  -  [C_0805NEW]  27.04 63.19 0 top
CI22  -  [C_0402NEW]  23.45 30.36 0 top
CI23  -  [C_0805NEW]  22.74 31.7 0 top
CI24  -  [C_0402NEW]  16.36 34.17 180 top
CI25  -  [C_0402NEW]  209.07 41.46 90 top
CI26  -  [C_0402NEW]  31.19 55 0 top
CI27  -  [C_0805NEW]  22.74 33.41 0 top
CI30  -  [C_0402NEW]  208.23 40.52 0 top
CI31  -  [C_0805NEW]  208.35 39.19 0 top
CI32  -  [C_0402NEW]  209.07 44.16 270 top
CI40  -  [C_0603NEW]  20.29 64.53 270 bottom
CI43  -  [C_0603NEW]  17.36 53.1 90 bottom
CI44  -  [C_0603NEW]  14.32 32.33 90 bottom
CL15  -  [C_0402NEW]  34.2 80.27 180 bottom
CL19  -  [C_0402NEW]  42.95 82.45 270 bottom
CL20  -  [C_0402NEW]  35.97 80.29 270 bottom
CL22  -  [C_0402NEW]  34.2 87.64 180 bottom
CL26  -  [C_0402NEW]  34.2 88.53 180 bottom
CL30  -  [C_0402NEW]  42.07 88.16 270 bottom
CL31  -  [C_0402NEW]  42.95 88.16 270 bottom
CL33  -  [C_1206NEW]  19.22 79.78 270 top
CL34  -  [C_0402NEW]  35.97 88.2 90 bottom
CL35  -  [C_0402NEW]  35.08 88.2 90 bottom
CL36  -  [C_0402NEW]  37.24 80.41 270 bottom
CL37  -  [C_0402NEW]  38.57 79.44 90 bottom
CL38  -  [C_0603NEW]  47.32 85.16 0 bottom
CL39  -  [C_0402NEW]  43.78 80.47 180 bottom
CL41  -  [C_0402NEW]  32.48 83.75 90 bottom
CM40  -  [C_0402NEW]  94.31 146.19 0 top
CM43  -  [C_0603NEW]  112.68 148.32 0 top
CM44  -  [C_0402NEW]  109.33 147.73 90 top
CM46  -  [C_0402NEW]  116.87 147.7 90 top
CM47  -  [C_0402NEW]  105.69 147.76 90 top
CM48  -  [C_0402NEW]  111.73 147.74 90 top
CM49  -  [C_0402NEW]  108.45 147.73 90 top
CMOS1  -  [SHORTPADS]  113.18 40.16 0 bottom
CR1  -  [C_0402NEW]  177.98 18.06 270 top
CR2  -  [C_0603NEW]  179.06 17.98 270 top
CR3  -  [C_0402NEW]  180.14 17.14 90 top
CR4  -  [C_0402NEW]  172.42 22.17 0 top
CR5  -  [C_0402NEW]  181.79 21.83 180 top
CR6  -  [C_0402NEW]  177.32 28.03 270 top
CR7  -  [C_0402NEW]  182.26 28.59 0 top
CR8  -  [C_0603NEW]  189.26 29.16 270 top
CR9  -  [C_0402NEW]  179.58 27.13 90 top
CR10  -  [C_0402NEW]  181.77 23.61 270 top
CR11  -  [C_0402NEW]  175.16 26.99 90 top
CS5  -  [C_0402NEW]  220.75 63.17 90 top
CS6  -  [C_0402NEW]  219.87 63.17 90 top
CS7  -  [C_0805NEW]  218.86 62.08 180 top
CS8  -  [C_0402NEW]  222.64 100.36 180 bottom
CS9  -  [C_0402NEW]  222.64 101.25 180 bottom
CS10  -  [C_0402NEW]  223.18 113.49 180 bottom
CS11  -  [C_0402NEW]  223.18 112.6 180 bottom
CS12  -  [C_0805NEW]  223 111.2 180 bottom
CS13  -  [C_0402NEW]  219.5 118.18 180 bottom
CS14  -  [C_0402NEW]  222.64 103.5 180 bottom
CS15  -  [C_0402NEW]  222.64 104.39 180 bottom
CS16  -  [C_0603NEW]  221.83 122.68 0 bottom
CS17  -  [C_0402NEW]  222.93 105.47 180 bottom
CS105  -  [C_0402NEW]  224.39 38.36 180 top
CS106  -  [C_0402NEW]  224.39 39.25 180 top
CS108  -  [C_0402NEW]  224.39 41.03 180 top
CS109  -  [C_0402NEW]  224.39 40.14 180 top
CV1  -  [C_0603NEW]  196.62 156.54 90 top
CV3  -  [C_0603NEW]  195.42 156.54 90 top
CV4  -  [C_0603NEW]  218.53 122.38 0 top
CV5  -  [C_0603NEW]  218.53 123.58 0 top
CV6  -  [C_0603NEW]  218.02 102.12 270 top
CV7  -  [C_0603NEW]  216.82 102.12 270 top
CV8  -  [C_0402NEW]  164.43 156.21 90 top
CV9  -  [C_0402NEW]  163.54 156.21 90 top
CV10  -  [C_0402NEW]  194.85 156.14 90 bottom
CV11  -  [C_0402NEW]  193.13 156.33 90 top
CV12  -  [C_0402NEW]  219.03 131.96 0 top
CV13  -  [C_0402NEW]  218.52 141.3 0 bottom
CV14  -  [C_0402NEW]  165.89 156.21 90 bottom
CV15  -  [C_0402NEW]  164.81 156.21 90 bottom
CV16  -  [C_0402NEW]  163.92 156.21 90 bottom
CV17  -  [C_0402NEW]  173.7 156.53 90 bottom
CV18  -  [C_0402NEW]  219.48 143.09 270 bottom
CV19  -  [C_0402NEW]  218.46 127.33 0 bottom
CV20  -  [C_0402NEW]  218.46 125.55 0 bottom
CV21  -  [C_0402NEW]  200.5 131.01 0 bottom
CV22  -  [C_0402NEW]  201.41 132.79 180 bottom
CV23  -  [C_0402NEW]  218.71 125.55 0 top
CV24  -  [C_0402NEW]  219.62 127.33 180 top
CV25  -  [C_0402NEW]  205.51 142.62 90 top
CV26  -  [C_0402NEW]  203.74 143.53 270 top
CV27  -  [C_0402NEW]  201.46 130.97 180 top
CV28  -  [C_0402NEW]  200.55 128.34 0 top
CV29  -  [C_0402NEW]  212.64 101.17 180 bottom
CV30  -  [C_0402NEW]  211.73 99.39 0 bottom
CV31  -  [C_0402NEW]  205.26 101.81 270 bottom
CV32  -  [C_0402NEW]  203.48 100.9 90 bottom
CV33  -  [C_0402NEW]  201.22 112.77 180 top
CV34  -  [C_0402NEW]  200.31 114.55 0 top
CV35  -  [C_0402NEW]  213.64 100.1 270 top
CV36  -  [C_0402NEW]  211.86 99.18 90 top
CV37  -  [C_0402NEW]  218.46 119.2 0 top
CV38  -  [C_0402NEW]  218.46 117.42 0 top
CV39  -  [C_0402NEW]  201.22 112.77 180 bottom
CV40  -  [C_0402NEW]  200.31 114.55 0 bottom
CV41  -  [C_0603NEW]  167.01 156.28 90 bottom
CV42  -  [C_0603NEW]  162.78 156.16 90 bottom
CV43  -  [C_0402NEW]  159.08 117.61 0 top
CV44  -  [C_0402NEW]  159.08 116.72 0 top
CV45  -  [C_0402NEW]  160.92 118.76 0 top
CV46  -  [C_0402NEW]  160.92 117.87 0 top
CV47  -  [C_0402NEW]  159.08 119.96 0 top
CV48  -  [C_0402NEW]  159.08 119.07 0 top
CV49  -  [C_0402NEW]  160.92 120.22 0 top
CV50  -  [C_0402NEW]  160.92 121.11 0 top
CV59  -  [C_0402NEW]  173.7 156.53 90 top
CV60  -  [C_0402NEW]  172.81 156.53 90 top
CV61  -  [C_0402NEW]  170.97 156.21 90 top
CV62  -  [C_0402NEW]  188.69 156.27 90 top
CV63  -  [C_0402NEW]  189.32 156.14 90 bottom
CV64  -  [C_0402NEW]  186.91 156.27 90 top
CV65  -  [C_0402NEW]  187.93 156.14 90 bottom
CV66  -  [C_0402NEW]  185.96 156.27 90 top
CV67  -  [C_0402NEW]  187.04 156.14 90 bottom
CV68  -  [C_0402NEW]  185.07 156.27 90 top
CV69  -  [C_0402NEW]  170.08 156.21 90 top
CV70  -  [C_0402NEW]  169.07 156.21 90 top
CV71  -  [C_0402NEW]  168.18 156.21 90 top
CV72  -  [C_0402NEW]  166.78 156.21 90 top
CV73  -  [C_0402NEW]  165.89 156.21 90 top
CV74  -  [C_0402NEW]  186.15 156.14 90 bottom
CV75  -  [C_0402NEW]  166.09 114.06 270 top
CV76  -  [C_0402NEW]  165.2 114.06 270 top
CV77  -  [C_0603NEW]  163.73 113.22 270 top
CV78  -  [C_0402NEW]  165.2 115.84 270 top
CV79  -  [C_0402NEW]  166.09 115.84 270 top
CV80  -  [C_0603NEW]  163.73 115.64 270 top
CV81  -  [C_0402NEW]  185.01 102.24 180 bottom
CV82  -  [C_0603NEW]  161.7 105.35 90 bottom
CV83  -  [C_0402NEW]  170.45 108.97 0 top
CV84  -  [C_0402NEW]  170.45 109.86 0 top
CV85  -  [C_0402NEW]  179.86 94.57 270 bottom
CV86  -  [C_0603NEW]  161.7 104.33 270 bottom
CV87  -  [C_0402NEW]  170.57 105.92 0 top
CV88  -  [C_0402NEW]  170.57 106.81 0 top
CV89  -  [C_0402NEW]  178.03 92.65 180 bottom
CV91  -  [C_0603NEW]  158.52 107.57 180 bottom
CV92  -  [C_0402NEW]  158.6 105.54 180 bottom
CV93  -  [C_0402NEW]  158.6 106.49 180 bottom
CV94  -  [C_0402NEW]  170.54 101.16 180 bottom
CV95  -  [C_0402NEW]  171.4 101.16 0 bottom
CV97  -  [C_0805NEW]  166.59 126.16 90 top
CV101  -  [C_0603NEW]  182.21 93.73 90 bottom
CV102  -  [C_0603NEW]  180.94 93.73 90 bottom
CV103  -  [C_0603NEW]  188.18 94.81 270 bottom
CV108  -  [C_0402NEW]  174.22 106.68 180 top
CV109  -  [C_0402NEW]  174.6 109.16 180 top
CV110  -  [C_0603NEW]  161.7 104.33 270 top
CV111  -  [C_0603NEW]  182.27 100.21 180 bottom
CV112  -  [C_0402NEW]  182.34 101.3 180 bottom
CV113  -  [C_0402NEW]  182.34 102.19 180 bottom
CV114  -  [C_0402NEW]  160.55 105.91 90 top
CV115  -  [C_0402NEW]  159.6 105.91 90 top
CV116  -  [C_0603NEW]  158.52 105.99 90 top
CV117  -  [C_0603NEW]  185.95 100.28 0 bottom
CV118  -  [C_0402NEW]  185.88 102.24 0 bottom
CV119  -  [C_0402NEW]  185.88 101.35 0 bottom
CV120  -  [C_0603NEW]  157.63 104.4 270 top
CV121  -  [C_0402NEW]  159.61 104.43 270 top
CV122  -  [C_0402NEW]  158.72 104.43 270 top
CV123  -  [C_0603NEW]  158.65 101.22 270 top
CV124  -  [C_0402NEW]  160.62 101.22 270 top
CV125  -  [C_0402NEW]  159.73 101.22 270 top
CV126  -  [C_0402NEW]  155.79 112.54 270 top
CV127  -  [C_0402NEW]  156.68 112.54 270 top
CV128  -  [C_0402NEW]  155.22 114.23 90 top
CV129  -  [C_0402NEW]  156.17 114.23 90 top
CV130  -  [C_0402NEW]  157.57 112.54 270 top
CV131  -  [C_0603NEW]  154.65 113.1 270 top
CV132  -  [C_0402NEW]  161.13 115.94 90 bottom
CV133  -  [C_0402NEW]  162.02 115.94 90 bottom
CV134  -  [C_0603NEW]  159.73 114.62 90 bottom
CV135  -  [C_B2]  160.34 157.43 0 top
CV136  -  [C_0603NEW]  197.83 156.53 90 top
CV137  -  [C_0603NEW]  203.55 144.79 90 bottom
CV138  -  [C_0603NEW]  218.34 113.29 0 bottom
CV139  -  [C_0603NEW]  218.53 121.17 0 top
CV140  -  [C_0603NEW]  194.21 156.53 90 top
CV141  -  [C_0402NEW]  191.35 156.33 90 top
CV142  -  [C_0402NEW]  171.49 132.15 180 top
CV143  -  [C_0402NEW]  170.54 129.29 180 top
CV144  -  [C_0402NEW]  186.27 109.43 270 top
CV145  -  [C_0402NEW]  190.45 156.3 90 top
CV146  -  [C_0402NEW]  172.16 120.6 0 top
CV147  -  [C_0402NEW]  172.37 123.71 0 top
CV148  -  [C_0402NEW]  172.37 124.61 0 top
CV149  -  [C_0402NEW]  171.73 127.53 270 top
CV150  -  [C_0402NEW]  170.54 128.4 180 top
CV151  -  [C_0603NEW]  170.65 127.46 270 top
CV152  -  [C_0402NEW]  162.21 156.21 90 top
CV153  -  [C_0402NEW]  171.49 133.04 180 top
CV154  -  [C_0402NEW]  188.3 109.11 0 top
CV155  -  [C_0402NEW]  188.38 113.29 180 top
CV156  -  [C_0402NEW]  186.08 117.71 270 top
CV170  -  [C_0603NEW]  171.03 96.73 270 bottom
CV171  -  [C_0402NEW]  173.06 96.73 270 bottom
CV172  -  [C_0402NEW]  172.18 96.73 270 bottom
CV173  -  [C_0402NEW]  173.58 114.78 270 top
CV174  -  [C_0402NEW]  172.68 114.78 270 top
CV187  -  [C_0603NEW]  177.19 113.41 270 top
CV188  -  [C_0402NEW]  176.19 113.48 180 top
CV189  -  [C_0402NEW]  175.43 112.59 180 top
CV190  -  [C_0402NEW]  175.28 114.82 0 top
CV193  -  [C_0402NEW]  186.59 113.68 270 top
CV194  -  [C_0402NEW]  185.95 114.99 90 top
CV195  -  [C_0402NEW]  174.52 124.52 0 top
CV196  -  [C_0402NEW]  174.52 123.63 0 top
CV197  -  [C_0603NEW]  202.39 147.6 0 top
CV198  -  [C_0402NEW]  202.89 146.45 0 top
CV199  -  [C_0402NEW]  202.89 145.44 0 top
CV200  -  [C_0603NEW]  190.78 95.83 0 bottom
CV201  -  [C_0402NEW]  191.14 97.81 0 bottom
CV202  -  [C_0402NEW]  191.14 96.92 0 bottom
CV203  -  [C_0402NEW]  183.54 120.7 0 top
CV204  -  [C_0402NEW]  184.25 122.83 90 top
CV205  -  [C_0402NEW]  183.49 119.76 0 top
CV206  -  [C_0402NEW]  183.48 125.93 90 top
CV207  -  [C_0402NEW]  179.54 125.62 0 top
CV208  -  [C_0402NEW]  183.51 121.59 0 top
CV209  -  [C_0402NEW]  184.45 124.61 180 top
CV210  -  [C_0402NEW]  179.57 126.51 0 top
CV211  -  [C_0402NEW]  182.6 125.93 90 top
CV212  -  [C_0402NEW]  181.33 125.55 90 top
CV213  -  [C_0603NEW]  182.75 107.48 270 top
CV214  -  [C_0603NEW]  181.54 107.48 270 top
CV215  -  [C_0603NEW]  194.59 95.83 180 bottom
CV216  -  [C_0402NEW]  194.28 96.92 180 bottom
CV217  -  [C_0402NEW]  194.28 97.81 180 bottom
CV218  -  [C_0402NEW]  194.35 94.3 180 top
CV219  -  [C_0402NEW]  191.53 92.46 0 top
CV220  -  [C_0402NEW]  161.11 128.85 0 bottom
CV221  -  [C_0402NEW]  161.11 133.35 0 bottom
CV222  -  [C_0402NEW]  209.07 99.05 90 top
CV223  -  [C_0402NEW]  196.2 103.27 90 bottom
CV224  -  [C_0402NEW]  196.18 105.95 270 bottom
CV280  -  [C_0402NEW]  218.52 138.95 0 bottom
CV281  -  [C_0402NEW]  218.52 138.06 0 bottom
CV283  -  [C_0402NEW]  218.52 136.6 0 bottom
CV284  -  [C_0402NEW]  218.52 135.71 0 bottom
CV285  -  [C_0402NEW]  218.52 134.44 0 bottom
CV286  -  [C_0402NEW]  218.52 133.55 0 bottom
CV287  -  [C_0402NEW]  218.52 131.77 0 bottom
CV288  -  [C_0402NEW]  218.52 130.88 0 bottom
CV290  -  [C_0402NEW]  218.52 130 0 bottom
CV291  -  [C_0402NEW]  219.03 131.07 0 top
CV292  -  [C_0402NEW]  219.03 132.85 0 top
CV293  -  [C_0402NEW]  219.03 129.3 0 top
CV294  -  [C_0402NEW]  219.03 128.41 0 top
CV295  -  [C_0402NEW]  218.46 123.75 0 bottom
CV296  -  [C_0402NEW]  218.46 122.86 0 bottom
CV297  -  [C_0402NEW]  218.52 129.11 0 bottom
CV298  -  [C_0402NEW]  218.33 113.87 0 top
CV299  -  [C_0402NEW]  218.33 114.76 0 top
CV301  -  [C_0402NEW]  218.33 109.29 0 bottom
CV302  -  [C_0402NEW]  218.33 110.18 0 bottom
CV303  -  [C_0402NEW]  218.39 112.15 0 bottom
CV304  -  [C_0402NEW]  218.33 104.6 0 bottom
CV305  -  [C_0402NEW]  218.71 105.61 0 top
CV306  -  [C_0402NEW]  218.77 107.83 0 top
CV307  -  [C_0402NEW]  218.77 110.18 0 top
CV308  -  [C_0402NEW]  218.33 111.58 0 top
CV310  -  [C_0402NEW]  218.39 115.64 0 top
CV311  -  [C_0402NEW]  218.39 116.53 0 top
CV312  -  [C_0402NEW]  218.39 111.26 0 bottom
CV313  -  [C_0402NEW]  218.33 107.83 0 bottom
CV315  -  [C_0402NEW]  218.33 106.94 0 bottom
CV316  -  [C_0402NEW]  218.33 105.48 0 bottom
CV318  -  [C_0402NEW]  218.71 104.72 0 top
CV319  -  [C_0402NEW]  218.77 109.29 0 top
CV322  -  [C_0603NEW]  183.99 117.88 270 top
CV323  -  [C_0603NEW]  180.32 107.46 270 top
CV324  -  [C_0603NEW]  177.77 125.43 90 top
CV325  -  [C_0402NEW]  180.21 111.46 180 top
CV326  -  [C_0402NEW]  161.82 109.68 270 bottom
CV327  -  [C_D2]  161.79 129.8 180 top
CV328  -  [C_0402NEW]  170.78 138.19 90 top
CV329  -  [C_0402NEW]  167.29 98.07 90 top
CV330  -  [C_0402NEW]  158.13 148.54 0 top
CV331  -  [C_0402NEW]  160.81 110.51 270 top
CV332  -  [C_0402NEW]  180.62 156.27 90 top
CV333  -  [C_0402NEW]  159.41 111.62 90 top
CV335  -  [C_0402NEW]  155.92 110.19 270 top
CV349  -  [C_0402NEW]  188.24 139.04 270 top
CV350  -  [C_0402NEW]  190.02 138.12 90 top
CV351  -  [C_0402NEW]  181.51 156.14 90 bottom
CV352  -  [C_0402NEW]  183.29 157.06 270 bottom
CV353  -  [C_0402NEW]  188.24 139.04 270 bottom
CV354  -  [C_0402NEW]  190.02 138.12 90 bottom
CV355  -  [C_0402NEW]  201.39 155.06 90 bottom
CV356  -  [C_0402NEW]  199.61 155.98 270 bottom
CV368  -  [C_0402NEW]  184.18 156.27 90 top
CV369  -  [C_0402NEW]  185.26 156.14 90 bottom
CV370  -  [C_0402NEW]  192.24 156.33 90 top
CV371  -  [C_0402NEW]  183.29 156.27 90 top
CV372  -  [C_0402NEW]  171.42 156.21 90 bottom
CV373  -  [C_0402NEW]  174.59 156.53 90 top
CV374  -  [C_0402NEW]  169.07 156.21 90 bottom
CV375  -  [C_0402NEW]  168.18 156.21 90 bottom
CV376  -  [C_0402NEW]  193.96 156.14 90 bottom
CV377  -  [C_0402NEW]  192.5 156.14 90 bottom
CV378  -  [C_0402NEW]  170.53 156.21 90 bottom
CV379  -  [C_0402NEW]  189.58 156.27 90 top
CV380  -  [C_0402NEW]  172.81 156.53 90 bottom
CV381  -  [C_0402NEW]  191.61 156.14 90 bottom
CV382  -  [C_0402NEW]  190.21 156.14 90 bottom
CV383  -  [C_0402NEW]  187.8 156.27 90 top
CV384  -  [C_0402NEW]  218.52 132.66 0 bottom
CV385  -  [C_0402NEW]  219.03 130.19 0 top
CV386  -  [C_0402NEW]  218.52 128.22 0 bottom
CV387  -  [C_0402NEW]  159.05 152.98 180 top
CV388  -  [C_0402NEW]  170.78 138.19 90 bottom
CV389  -  [C_0402NEW]  200.96 157.94 180 top
CV390  -  [C_0402NEW]  200.04 156.16 0 top
CV391  -  [C_0402NEW]  218.77 106.94 0 top
CV392  -  [C_0402NEW]  218.33 112.47 0 top
CV393  -  [C_0402NEW]  158.13 151.2 0 top
CV394  -  [C_0402NEW]  176.18 157.3 270 bottom
CV395  -  [C_0402NEW]  177.96 156.39 90 bottom
CV396  -  [C_0402NEW]  176.18 157.3 270 top
CV397  -  [C_0402NEW]  168.11 139.1 270 bottom
CV398  -  [C_0402NEW]  177.96 156.39 90 top
CV399  -  [C_0402NEW]  169 139.1 270 top
CV400  -  [C_0402NEW]  159.03 146.77 270 top
CV401  -  [C_0402NEW]  182.4 156.27 90 top
CX1  -  [C_0402NEW]  216.7 173.75 180 top
CX2  -  [C_0402NEW]  213.96 167.73 270 bottom
CX3  -  [C_0805NEW]  215.01 167.9 0 bottom
CX4  -  [C_0402NEW]  219.87 176.27 90 top
CX5  -  [C_0603NEW]  224.5 175.72 90 top
CX6  -  [C_0402NEW]  24.92 95.91 270 bottom
CX7  -  [C_0805NEW]  216.21 172.41 180 top
CX8  -  [C_0805NEW]  216.37 171.1 270 bottom
CX9  -  [C_0402NEW]  217.83 166.84 270 top
CX10  -  [C_0402NEW]  213.57 161.05 0 bottom
CX11  -  [C_0402NEW]  213.2 170.37 90 bottom
CX12  -  [C_0402NEW]  20.02 101.67 0 bottom
CX13  -  [C_0402NEW]  20.02 100.79 0 bottom
CX14  -  [C_0402NEW]  19.21 104.34 0 bottom
CX15  -  [C_0402NEW]  19.21 103.45 0 bottom
CX16  -  [C_0402NEW]  18.18 99.01 0 bottom
CX17  -  [C_0402NEW]  18.18 98.12 0 bottom
CX18  -  [C_0402NEW]  19.07 96.34 0 bottom
CX19  -  [C_0402NEW]  19.07 95.45 0 bottom
CX20  -  [C_0402NEW]  15.09 111.47 180 bottom
CX21  -  [C_0402NEW]  14.13 107.4 270 bottom
CX22  -  [C_0603NEW]  15.21 107.39 270 bottom
CX23  -  [C_0402NEW]  15.01 101.66 90 bottom
CX24  -  [C_0402NEW]  15.01 100.8 270 bottom
CX25  -  [C_0402NEW]  14.13 104.33 90 bottom
CX26  -  [C_0402NEW]  14.13 103.46 270 bottom
CX27  -  [C_0402NEW]  13.11 99.06 90 bottom
CX28  -  [C_0402NEW]  13.11 98.19 270 bottom
CX29  -  [C_0402NEW]  14 96.39 90 bottom
CX30  -  [C_0402NEW]  14 95.53 270 bottom
CX31  -  [C_0402NEW]  199.04 170.9 180 bottom
CX32  -  [C_0402NEW]  199.6 167.6 180 top
CX33  -  [C_0402NEW]  199.04 170.03 180 bottom
CX34  -  [C_0402NEW]  203.99 165.31 270 top
CX35  -  [C_0603NEW]  198.09 168.98 180 bottom
CX36  -  [C_0805NEW]  206.82 164.86 0 top
CX37  -  [C_0402NEW]  204.88 175.58 90 top
CX38  -  [C_0402NEW]  196.74 169.2 0 top
CX39  -  [C_0402NEW]  196.74 168.31 0 top
CX40  -  [C_0402NEW]  204.64 163.02 180 top
CX41  -  [C_0402NEW]  205.77 165.31 270 top
CX42  -  [C_0402NEW]  198.52 170.38 0 top
CX43  -  [C_0402NEW]  198.52 171.27 0 top
CX44  -  [C_0402NEW]  198.52 172.16 0 top
CX45  -  [C_0603NEW]  204.56 161.81 180 top
CX46  -  [C_0402NEW]  198.52 169.49 0 top
CX47  -  [C_0402NEW]  199.33 161.78 180 top
CX48  -  [C_0805NEW]  198.92 163.45 90 top
DA8  -  [BAT54C-7-F_SOT23-3]  38.13 25.32 0 top
DA10  -  [AZ5125-02SPR7G_SOT23-3]  18.13 11.19 90 top
DA12  -  [AZ5125-02SPR7G_SOT23-3]  16.44 14.46 0 top
DC1  -  [BAT54CW_SOT323-3]  203.31 13.16 180 bottom
DE1  -  [L03ESDL5V0CG3-2_SOT-523-3]  171.4 44.32 0 top
DH1  -  [RB751V-40_SOD323-2]  144.25 117.62 270 bottom
DI1  -  [IP4292CZ10-TBR_XSON10_2P5X1]  16.69 59.91 90 bottom
DI2  -  [L30ESDL5V0C3-2_SOT23-3]  17.09 57.03 90 bottom
DI4  -  [IP4292CZ10-TBR_XSON10_2P5X1]  17.51 46.76 90 bottom
DI5  -  [L30ESDL5V0C3-2_SOT23-3]  16.58 44.27 90 bottom
DI7  -  [L30ESDL5V0C3-2_SOT23-3]  15.04 27.89 90 bottom
DX1  -  [RB751V-40_SOD323-2]  219.42 165.64 270 bottom
FD1  -  [FIDUCIAL_C40M80]  226.98 161.94 180 bottom
FD2  -  [FIDUCIAL_C40M80]  16.35 9.6 180 bottom
FD3  -  [FIDUCIAL_C40M80]  39.46 14.04 0 top
FD4  -  [FIDUCIAL_C40M80]  227.42 177.37 0 top
FX1  -  [F_1206L150PR]  14.31 108.98 0 bottom
H2  -  [H_2P8]  109.2 13.4 0 top
H4  -  [H_2P8]  19.2 71.9 0 top
H5  -  [H_2P8]  21.9 4.9 0 top
H6  -  [H_3P3]  204.1 94.4 0 top
H7  -  [H_3P3]  153.3 144.5 0 top
H8  -  [H_2P8]  225.2 81.4 0 top
H9  -  [H_2P8]  225.2 168.4 0 top
H10  -  [H_3P3]  26.92 119.1 0 top
H11  -  [H_2P8]  164.2 185.4 0 top
H12  -  [H_2P8]  31.2 109.4 0 top
H16  -  [H_2P8]  127.6 154.8 0 top
H17  -  [H_2P8]  225.2 4.9 0 top
H18  -  [H_3P3]  19.2 38.1 0 top
H31  -  [H_3P7]  80.8 129.06 0 top
H32  -  [H_3P7]  141.2 103.66 0 top
H33  -  [H_3P7]  141.2 129.06 0 top
H34  -  [H_3P7]  80.8 103.66 0 top
H35  -  [H_3P7X3P2N]  195.55 187.5 0 top
J9  -  [JUMP_43X39]  185.84 86.5 180 bottom
J510  -  [JUMP_43X79]  100.59 31.57 180 bottom
J511  -  [JUMP_43X79]  92.63 31.57 0 bottom
J513  -  [JUMP_43X79]  139.79 27.23 270 top
JDB  -  [JESS_UCNR2210M008-0_8P]  210.6 45.7 270 top
JDIMM1  -  [LCN_DAN06-K4406-0102_204P]  41.8 71.4 0 bottom
JDIMM2  -  [LCN_DAN06-K4406-0102_204P]  120.35 71.44 0 bottom
JFAN  -  [ACES_85204-0300N_3P]  48.69 108.61 0 bottom
JHDD  -  [SANTA_193202-1_22P]  227.22 37.39 270 bottom
JHDMI  -  [LOTES_ABA-HDM-022-K01_19P]  8.08 99.15 270 bottom
JHP  -  [SINGA_2SJ3080-000111F_6P-T]  11.75 8.09 270 bottom
JKB  -  [HB_A823020-SBHR21_30P]  228.6 159.82 270 top
JLAN  -  [SANTA_130456-311_8P]  15 79.23 90 bottom
JLVDS  -  [STARC_107K40-000001-G2_40P]  204.45 173.45 0 bottom
JMINI  -  [CONCR_525B01BE17A_52P]  93.3 150.67 0 bottom
JODD  -  [SANTA_202801-1_13P]  227.05 98.22 270 bottom
JP3  -  [JUMP_43X39]  45.16 85.29 0 bottom
JP7  -  [JUMP_43X79]  220.21 115.83 0 bottom
JP8  -  [JUMP_43X39]  182.13 91.57 0 bottom
JP9  -  [JUMP_43X39]  214.01 151.26 0 bottom
JP12  -  [JUMP_43X39]  200.49 12.46 0 bottom
JP13  -  [JUMP_43X79]  219.31 60.09 270 top
JPWR  -  [HB_A090420-SAHR21_4P]  45.34 95.4 180 top
JREAD  -  [T-SOL_143-2300302602_22P_RV]  191.48 29.92 180 bottom
JRTC  -  [LOTES_AAA-BAT-054-K01_2P]  210.2 9.4 270 bottom
JSPK  -  [E-T_3703-Q04N-11R_4P]  69.77 21.88 90 top
JTOUCH  -  [ACES_88460-00601-P01_6P]  23.71 96.89 180 top
JTP  -  [PS_HPF10052-06M000R_6P]  66.35 110.35 0 top
JUSB1  -  [ACON_TARA4-9K1311_9P]  12.69 67.1 90 bottom
JUSB2  -  [ACON_TARA4-9K1311_9P]  12.69 49.5 90 bottom
JUSB3  -  [ACON_UARBG-4K1926_4P]  10.32 31.9 90 bottom
JXDP1  -  [SAMTE_BSH-030-01-L-D-A_60P]  73.2 93.43 180 bottom
L1  -  [MURAT_LQM2MPN2R2NG0L_2P]  119.54 137.4 270 bottom
L2  -  [MURAT_LQM2MPN2R2NG0L_2P]  121.02 141.62 0 bottom
L3  -  [MURAT_LQM2MPN2R2NG0L_2P]  123.88 138.89 0 bottom
L4  -  [MURAT_LQM2MPN2R2NG0L_2P]  121.76 139.88 270 bottom
L5  -  [MURAT_LQM2MPN2R2NG0L_2P]  117.31 137.4 270 bottom
LA3  -  [R_0603NEW]  64.04 20.71 0 top
LA4  -  [R_0603NEW]  64.04 21.92 0 top
LA5  -  [R_0603NEW]  63.08 23.7 0 top
LA6  -  [R_0603NEW]  63.08 24.9 0 top
LA7  -  [KC_FBMA-L10-160808-800LMT_2P]  15.59 20.28 90 top
LA8  -  [KC_FBMA-L10-160808-800LMT_2P]  23.41 11.1 0 top
LA9  -  [KC_FBMA-L10-160808-800LMT_2P]  23.41 12.62 0 top
LA10  -  [KC_FBMA-L10-160808-800LMT_2P]  17.11 20.28 90 top
LE1  -  [KC_FBMA-L11-160808-800LMT_2P]  199.62 35.7 0 top
LE2  -  [KC_FBMA-L11-160808-800LMT_2P]  194.21 55.5 270 top
LED1  -  [LED_12-21C-T3D-CM2P1B18X-2C_3P]  31.81 10.74 0 top
LED2  -  [LED_12-21C-T3D-CM2P1B18X-2C_3P]  40.8 10.74 0 top
LED3  -  [LED_HT-210UD5-BP5_3P]  46.9 10.74 0 top
LED4  -  [LED_12-21C-T3D-CM2P1B18X-2C_3P]  58.81 10.7 0 top
LI1  -  [MURAT_DLW21SN670HQ2L_4P]  21.26 59.49 180 bottom
LI2  -  [KC_WCM-2012HS-900T_4P]  22.85 57.43 180 bottom
LI3  -  [MURAT_DLW21SN670HQ2L_4P]  21.26 61.4 180 bottom
LI4  -  [MURAT_DLW21SN670HQ2L_4P]  22.34 46.16 180 bottom
LI5  -  [KC_WCM-2012HS-900T_4P]  22.85 44.61 180 bottom
LI6  -  [MURAT_DLW21SN670HQ2L_4P]  22.34 47.93 180 bottom
LI7  -  [KC_WCM-2012HS-900T_4P]  20.75 27.91 180 bottom
LI10  -  [KC_WCM-2012HS-900T_4P]  205.68 49.12 0 top
LR2  -  [KC_WCM-2012HS-900T_4P]  171.95 33.05 180 bottom
LV12  -  [R_0402NEW]  162.59 112.64 270 top
LV13  -  [R_0402NEW]  162.59 115.14 270 top
LV14  -  [R_0402NEW]  160.55 106.19 270 bottom
LV15  -  [R_0402NEW]  160.55 103.84 270 bottom
LV16  -  [R_0402NEW]  159.54 105.27 90 bottom
LV17  -  [CHENG_MBK1608121YZF_2P]  153.38 111.28 90 top
LV18  -  [CHENG_MBK1608121YZF_2P]  156.77 114.75 0 bottom
LV19  -  [R_0402NEW]  169.05 96.73 0 bottom
LV20  -  [R_0402NEW]  184.1 99.51 0 bottom
LV21  -  [KC_FBMA-L11-160808-800LMT_2P]  203.72 148.99 180 top
LV22  -  [R_0402NEW]  191.75 94.75 180 bottom
LV23  -  [KC_FBMA-L11-160808-800LMT_2P]  194.21 92.92 90 bottom
LV25  -  [R_0402NEW]  180.95 113.1 180 top
LV26  -  [R_0402NEW]  182.28 114.68 180 top
LX1  -  [KC_FBMA-L11-201209-221LMA30_2P]  214.6 169.43 90 bottom
LX2  -  [KC_WCM-2012HS-900T_4P]  17.83 101.63 180 bottom
LX3  -  [KC_WCM-2012HS-900T_4P]  16.94 104.3 180 bottom
LX4  -  [KC_WCM-2012HS-900T_4P]  15.93 99.03 180 bottom
LX5  -  [KC_WCM-2012HS-900T_4P]  16.82 96.3 180 bottom
LX6  -  [KC_WCM-2012HS-900T_4P]  219.02 165.34 90 top
LX7  -  [KC_FBMA-L11-201209-221LMA30_2P]  205.96 162.89 270 top
LX8  -  [KC_FBMA-L11-201209-221LMA30_2P]  197.49 167.19 0 bottom
LX9  -  [CYNTE_PG031B-4R7MS_2P]  200.48 164.09 0 top
ME1  -  [SHORTPADS]  115.46 40.16 180 bottom
NOREF  -  []  164.2 185.4 0 top
NOREF#2  -  []  26.92 119.1 0 top
NOREF#3  -  []  21.9 4.9 0 top
NOREF#4  -  []  141.2 103.65 0 top
NOREF#5  -  []  109.2 13.4 0 top
NOREF#6  -  []  225.2 168.4 0 top
NOREF#7  -  []  141.2 129.05 0 top
NOREF#8  -  []  225.2 81.4 0 top
NOREF#9  -  []  127.6 154.8 0 top
NOREF#10  -  []  127.96 79.22 0 top
NOREF#11  -  []  32.86 216.61 0 top
NOREF#12  -  []  19.2 38.1 0 top
NOREF#13  -  []  38.32 50.56 0 top
NOREF#14  -  []  153.3 144.5 0 top
NOREF#15  -  []  74.32 49.5 0 top
NOREF#16  -  []  80.8 103.66 0 top
NOREF#17  -  []  108.36 -20.5 0 top
NOREF#18  -  []  204.1 94.4 0 top
NOREF#19  -  []  50.45 30.36 0 top
NOREF#20  -  []  80.8 129.06 0 top
NOREF#21  -  []  104.11 81.61 0 top
NOREF#22  -  []  225.2 4.9 0 top
NOREF#23  -  []  19.2 71.9 0 top
NOREF#24  -  []  123.09 42 0 top
NOREF#25  -  []  31.2 109.4 0 top
NOREF#26  -  []  137.89 89.16 180 bottom
NOREF#27  -  []  72.42 42.77 180 bottom
NOREF#28  -  []  158.78 39.19 180 bottom
NOREF#29  -  []  140.94 37.03 180 bottom
PBATT  -  [SUYIN_200028MR009G502ZL_9P]  139.52 188.7 0 bottom
PC1  -  [C_0402NEW]  139.79 179.89 90 bottom
PC2  -  [C_0402NEW]  140.68 179.89 90 bottom
PC3  -  [C_0402NEW]  138.71 168.49 270 top
PC4  -  [C_0402NEW]  137.82 168.49 270 top
PC5  -  [C_0402NEW]  129.54 171.91 180 top
PC7  -  [C_0402NEW]  158.07 181.05 0 bottom
PC8  -  [C_0402NEW]  158.07 182.19 0 bottom
PC13  -  [C_0402NEW]  130.85 180.8 180 top
PC14  -  [C_0402NEW]  132.11 164.49 270 top
PC15  -  [C_0402NEW]  127.54 163.57 90 top
PC16  -  [C_0402NEW]  127.47 167.32 90 top
PC100  -  [C_0603NEW]  119 13.19 90 top
PC101  -  [C_MP6VLPS220MC4R2]  137.7 18.26 0 bottom
PC102  -  [C_0402NEW]  129.82 12.06 90 top
PC103  -  [C_0603NEW]  132.68 21.25 180 top
PC104  -  [C_0402NEW]  131.52 15.79 0 top
PC105  -  [C_0603NEW]  128.54 18.07 180 bottom
PC106  -  [C_0603NEW]  127.58 20.18 180 bottom
PC107  -  [C_MP6VLPS220MC4R2]  117.94 18.43 180 bottom
PC108  -  [C_0402NEW]  126.67 12.99 270 bottom
PC109  -  [C_0603NEW]  127.82 12.92 270 top
PC110  -  [C_0402NEW]  123.21 16.39 0 top
PC111  -  [C_0603NEW]  121.63 21.46 0 top
PC112  -  [C_0805NEW]  128.58 25.41 270 bottom
PC113  -  [C_0402NEW]  126.33 25.55 270 top
PC114  -  [C_0402NEW]  127.23 25.58 270 top
PC115  -  [C_0805NEW]  128.58 25.41 270 top
PC200  -  [C_0603NEW]  154.91 21.68 0 bottom
PC201  -  [C_0402NEW]  163.8 14.95 270 bottom
PC202  -  [C_0402NEW]  162 24.33 0 bottom
PC203  -  [C_0402NEW]  162 26.11 0 bottom
PC204  -  [C_0603NEW]  159.67 20.03 90 bottom
PC205  -  [C_0805NEW]  154.91 27.14 270 bottom
PC206  -  [C_0805NEW]  159.86 16.36 270 bottom
PC207  -  [C_0402NEW]  156.42 11.19 0 bottom
PC208  -  [C_0402NEW]  162.91 14.95 270 bottom
PC209  -  [C_0603NEW]  160.88 21.42 270 bottom
PC210  -  [C_0402NEW]  159.67 28.22 90 bottom
PC211  -  [C_0805NEW]  156.88 28.6 0 bottom
PC212  -  [C_0805NEW]  161.57 16.36 270 bottom
PC213  -  [C_MP6VU330MC6]  146.34 22.44 0 bottom
PC300  -  [C_0402NEW]  148.17 150.12 0 bottom
PC301  -  [C_0603NEW]  139.23 150.5 90 bottom
PC302  -  [C_0603NEW]  148.43 158.05 180 bottom
PC303  -  [C_0402NEW]  143.42 157.28 90 bottom
PC304  -  [C_0402NEW]  142.53 157.28 90 bottom
PC305  -  [C_0805NEW]  141.32 155.16 270 bottom
PC306  -  [C_0805NEW]  139.61 155.16 270 bottom
PC307  -  [C_0402NEW]  147.74 153.72 90 bottom
PC308  -  [C_0805NEW]  141.7 142.35 90 top
PC309  -  [C_0805NEW]  143.41 142.35 90 top
PC310  -  [C_0805NEW]  146.84 142.35 90 top
PC311  -  [C_0805NEW]  145.13 142.35 90 top
PC312  -  [C_0603NEW]  147.04 155.64 0 bottom
PC313  -  [C_0603NEW]  144.5 157.48 0 bottom
PC400  -  [C_0805NEW]  112.85 29.6 270 bottom
PC401  -  [C_0402NEW]  107.44 25.89 0 bottom
PC402  -  [C_0805NEW]  111.14 29.6 270 bottom
PC403  -  [C_0402NEW]  111.9 26.85 270 bottom
PC404  -  [C_0402NEW]  113.68 24.69 270 bottom
PC405  -  [C_0805NEW]  107.9 23.13 90 bottom
PC501  -  [C_0402NEW]  117.2 138.82 180 bottom
PC502  -  [C_0402NEW]  113.82 145.06 270 bottom
PC503  -  [C_0603NEW]  82.9 135.39 90 bottom
PC504  -  [C_0402NEW]  86.95 136.35 0 top
PC505  -  [C_0603NEW]  90.14 131.66 0 bottom
PC506  -  [C_0402NEW]  88.74 136.29 270 top
PC507  -  [C_0402NEW]  89.94 135.38 90 top
PC508  -  [C_0603NEW]  89.69 142.7 270 bottom
PC509  -  [C_0402NEW]  90.26 139.85 270 top
PC510  -  [C_0402NEW]  93.89 139.08 180 bottom
PC511  -  [C_0402NEW]  93.89 139.96 180 bottom
PC512  -  [C_0402NEW]  86.95 135.46 0 top
PC513  -  [C_0402NEW]  92.66 134.38 0 bottom
PC514  -  [C_0402NEW]  91.79 132.66 90 bottom
PC515  -  [C_EEEFZ1E101P]  129.63 143.23 270 bottom
PC516  -  [C_EEEFZ1E101P]  136.74 143.16 270 bottom
PC517  -  [C_0805NEW]  116.93 143.24 90 top
PC518  -  [C_0805NEW]  116.93 143.24 90 bottom
PC519  -  [C_0402NEW]  114.71 144.14 90 bottom
PC520  -  [C_0402NEW]  107.22 142.81 90 top
PC521  -  [C_0402NEW]  115.6 144.14 90 bottom
PC522  -  [C_0402NEW]  85.46 139.9 180 bottom
PC600  -  [C_0805NEW]  217.87 98.25 0 top
PC601  -  [C_0402NEW]  216.61 92.66 0 bottom
PC602  -  [C_0805NEW]  217.87 96.21 0 top
PC603  -  [C_0402NEW]  220.06 93.37 270 top
PC604  -  [C_0402NEW]  222.16 88.02 180 bottom
PC605  -  [C_0805NEW]  217.14 89.96 90 bottom
PC701  -  [C_0603NEW]  143.03 169.17 270 bottom
PC702  -  [C_0402NEW]  143.81 166.63 180 bottom
PC703  -  [C_0805NEW]  157.7 166.24 0 top
PC704  -  [C_0805NEW]  157.7 164.46 0 top
PC705  -  [C_0402NEW]  158 168.86 0 top
PC706  -  [C_0603NEW]  157.83 167.78 0 top
PC707  -  [C_0603NEW]  167.41 167.65 0 bottom
PC708  -  [C_0402NEW]  166.4 167.46 90 bottom
PC709  -  [C_0603NEW]  164.68 172.54 180 top
PC710  -  [C_0603NEW]  163.92 167.08 180 top
PC711  -  [C_0402NEW]  172.25 168.1 180 top
PC712  -  [C_0805NEW]  146.63 179.72 0 top
PC713  -  [C_0805NEW]  146.63 181.43 0 top
PC714  -  [C_0805NEW]  145.93 175.97 0 top
PC715  -  [C_0402NEW]  154.13 176.5 0 top
PC716  -  [C_0805NEW]  146.63 183.14 0 top
PC717  -  [C_0402NEW]  167.75 165.94 180 top
PC718  -  [C_0805NEW]  145.93 174.25 0 top
PC719  -  [C_0402NEW]  169.64 174.06 270 top
PC720  -  [C_0402NEW]  195.61 51.71 270 bottom
PC721  -  [C_0603NEW]  162.53 168.35 0 top
PC722  -  [C_0402NEW]  167.73 175.14 0 top
PC723  -  [C_0402NEW]  171.99 177.11 180 top
PC724  -  [C_EEEFZ1E101P]  157.1 164.03 0 bottom
PC803  -  [C_0603NEW]  207.1 61.73 90 bottom
PC804  -  [C_0805NEW]  212.73 71.83 0 top
PC805  -  [C_0805NEW]  212.73 69.54 0 top
PC806  -  [C_0402NEW]  204.23 51.95 0 bottom
PC807  -  [C_0603NEW]  202.47 61.67 0 bottom
PC808  -  [C_0805NEW]  212.73 67.26 0 top
PC809  -  [C_0402NEW]  201.51 54.63 270 bottom
PC810  -  [C_0603NEW]  201.51 57.48 180 top
PC811  -  [C_0603NEW]  205.32 58.94 0 top
PC813  -  [C_0402NEW]  205.32 55.27 270 top
PC814  -  [C_0402NEW]  204.23 51.06 0 bottom
PC815  -  [C_0603NEW]  208.56 62.81 0 top
PC816  -  [C_0402NEW]  201.58 55.5 90 top
